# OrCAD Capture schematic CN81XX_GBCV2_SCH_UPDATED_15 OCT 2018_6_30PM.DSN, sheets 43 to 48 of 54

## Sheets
43 47.mSATA CONNECTOR0: size Custom; title: mSATA connector0
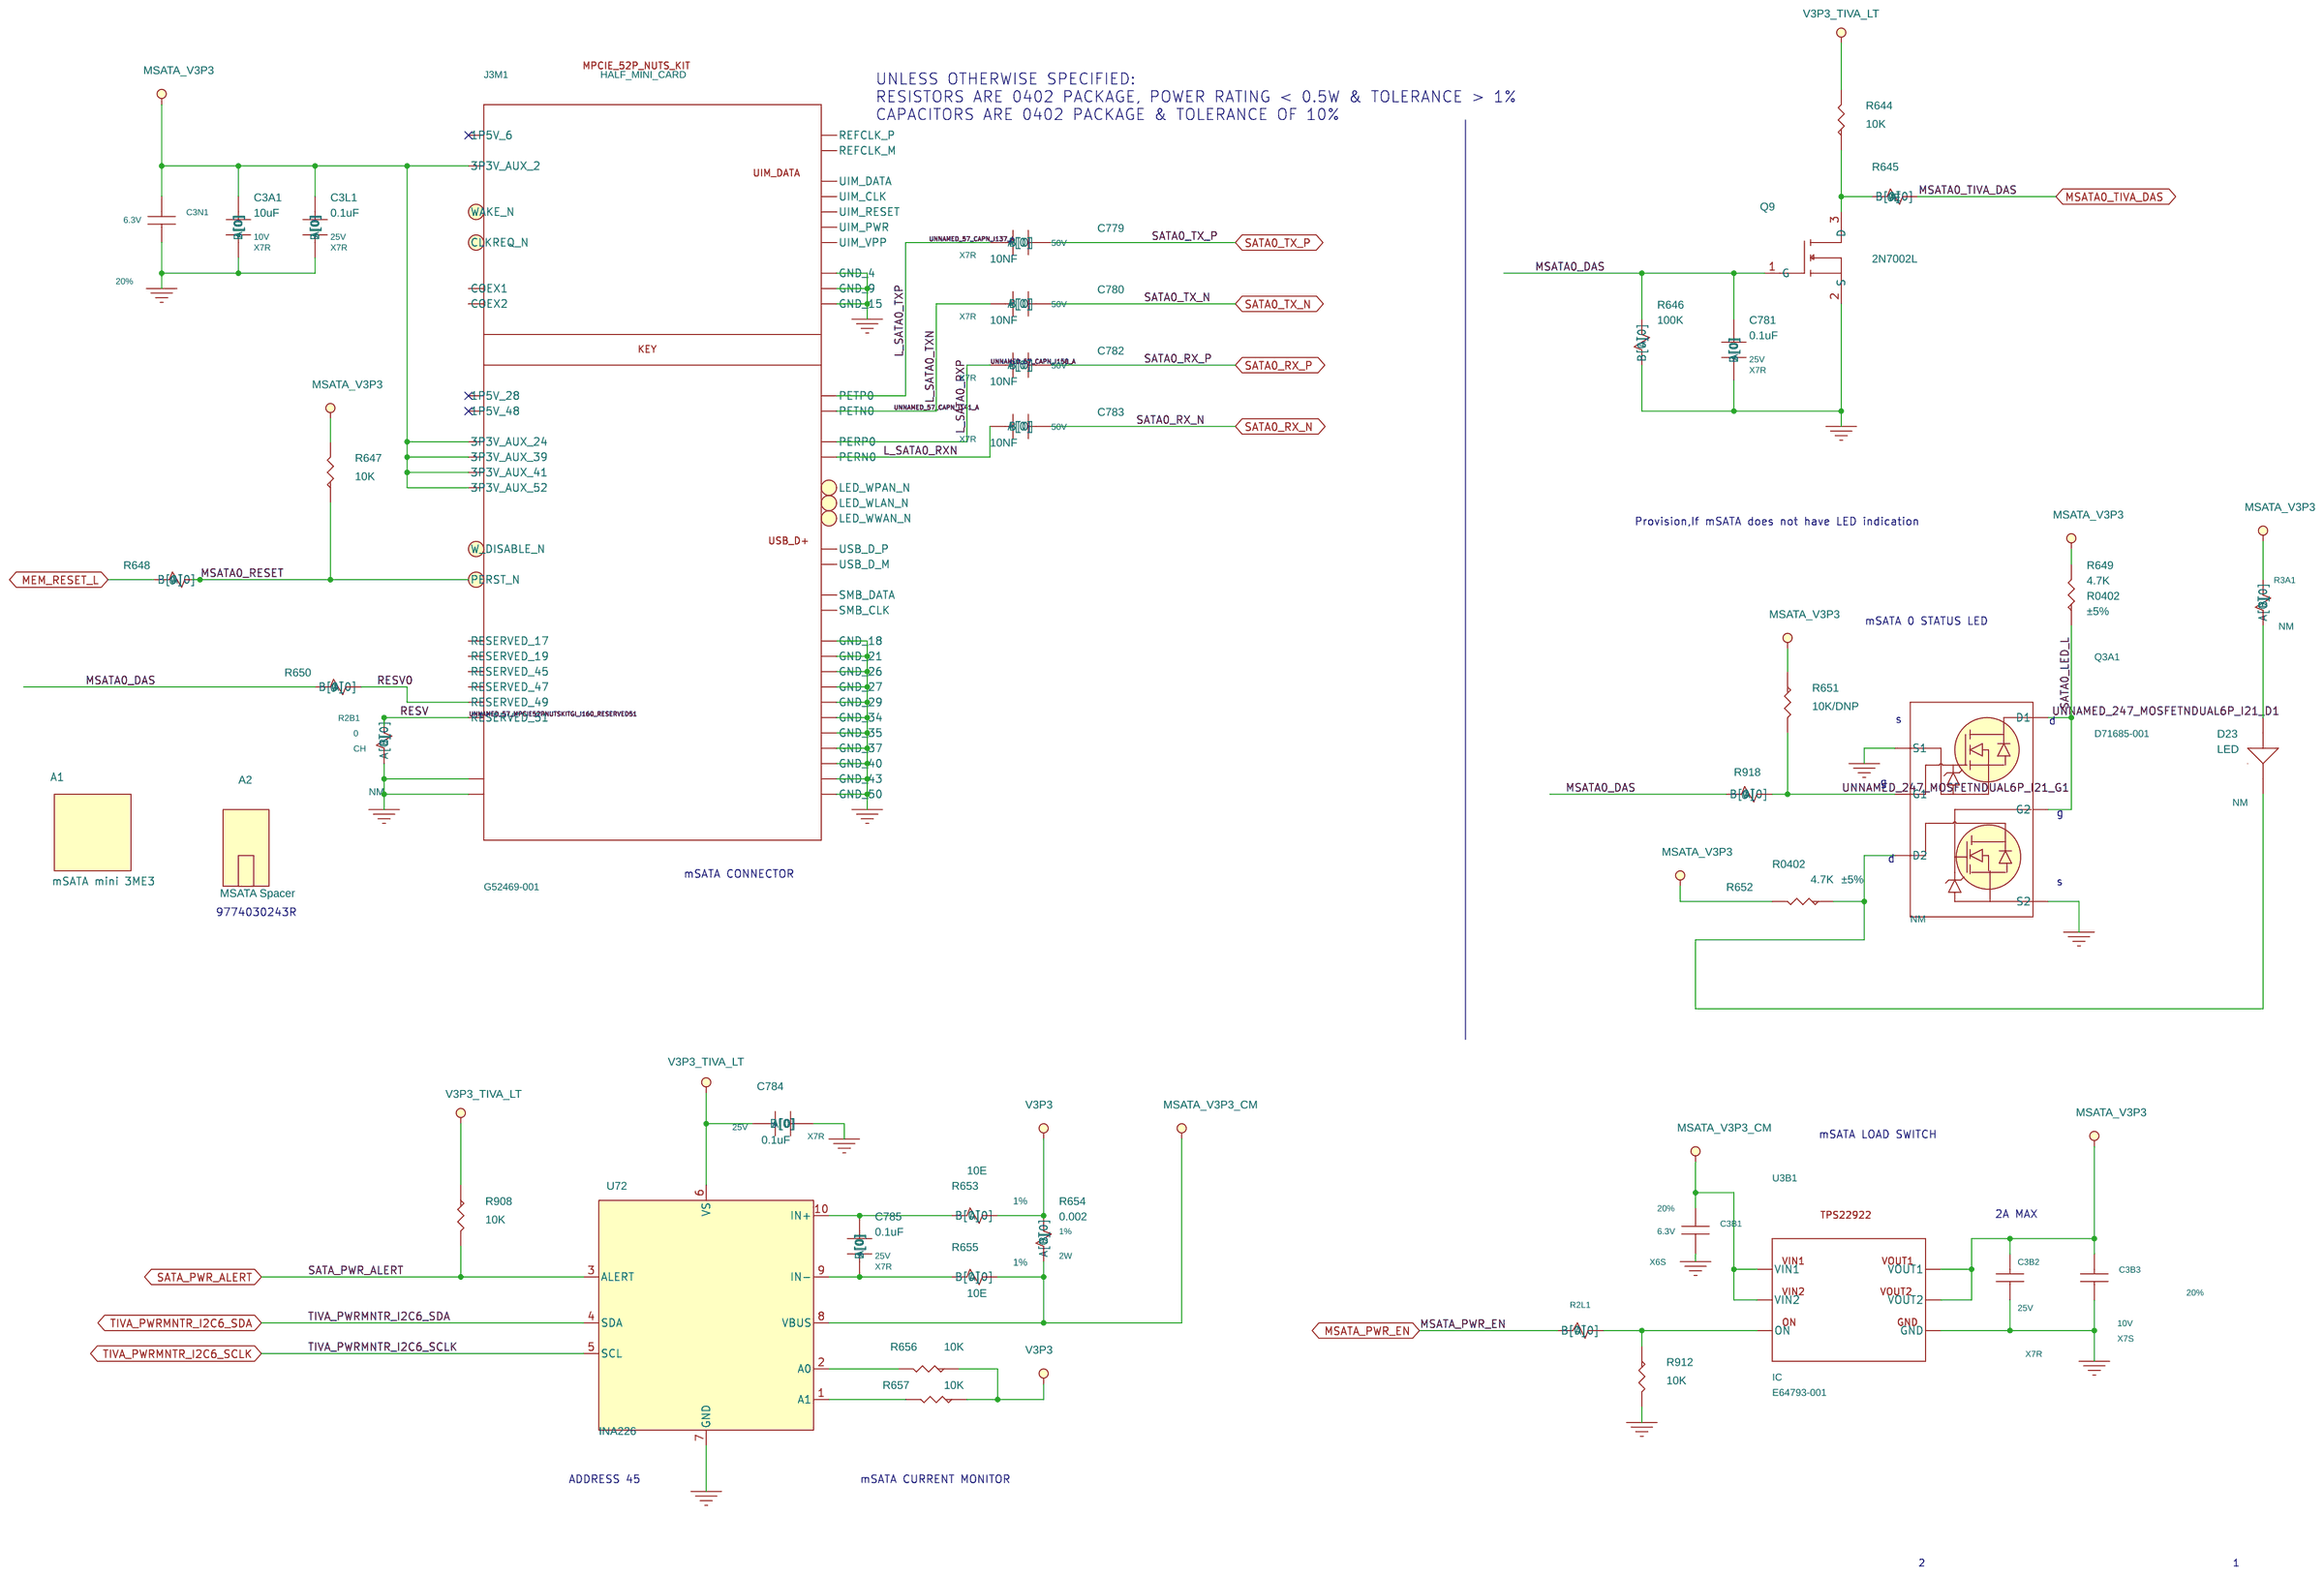
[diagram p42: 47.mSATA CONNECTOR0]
44 48. mSATA CONNECTOR1: size Custom; title: mSATA connector1
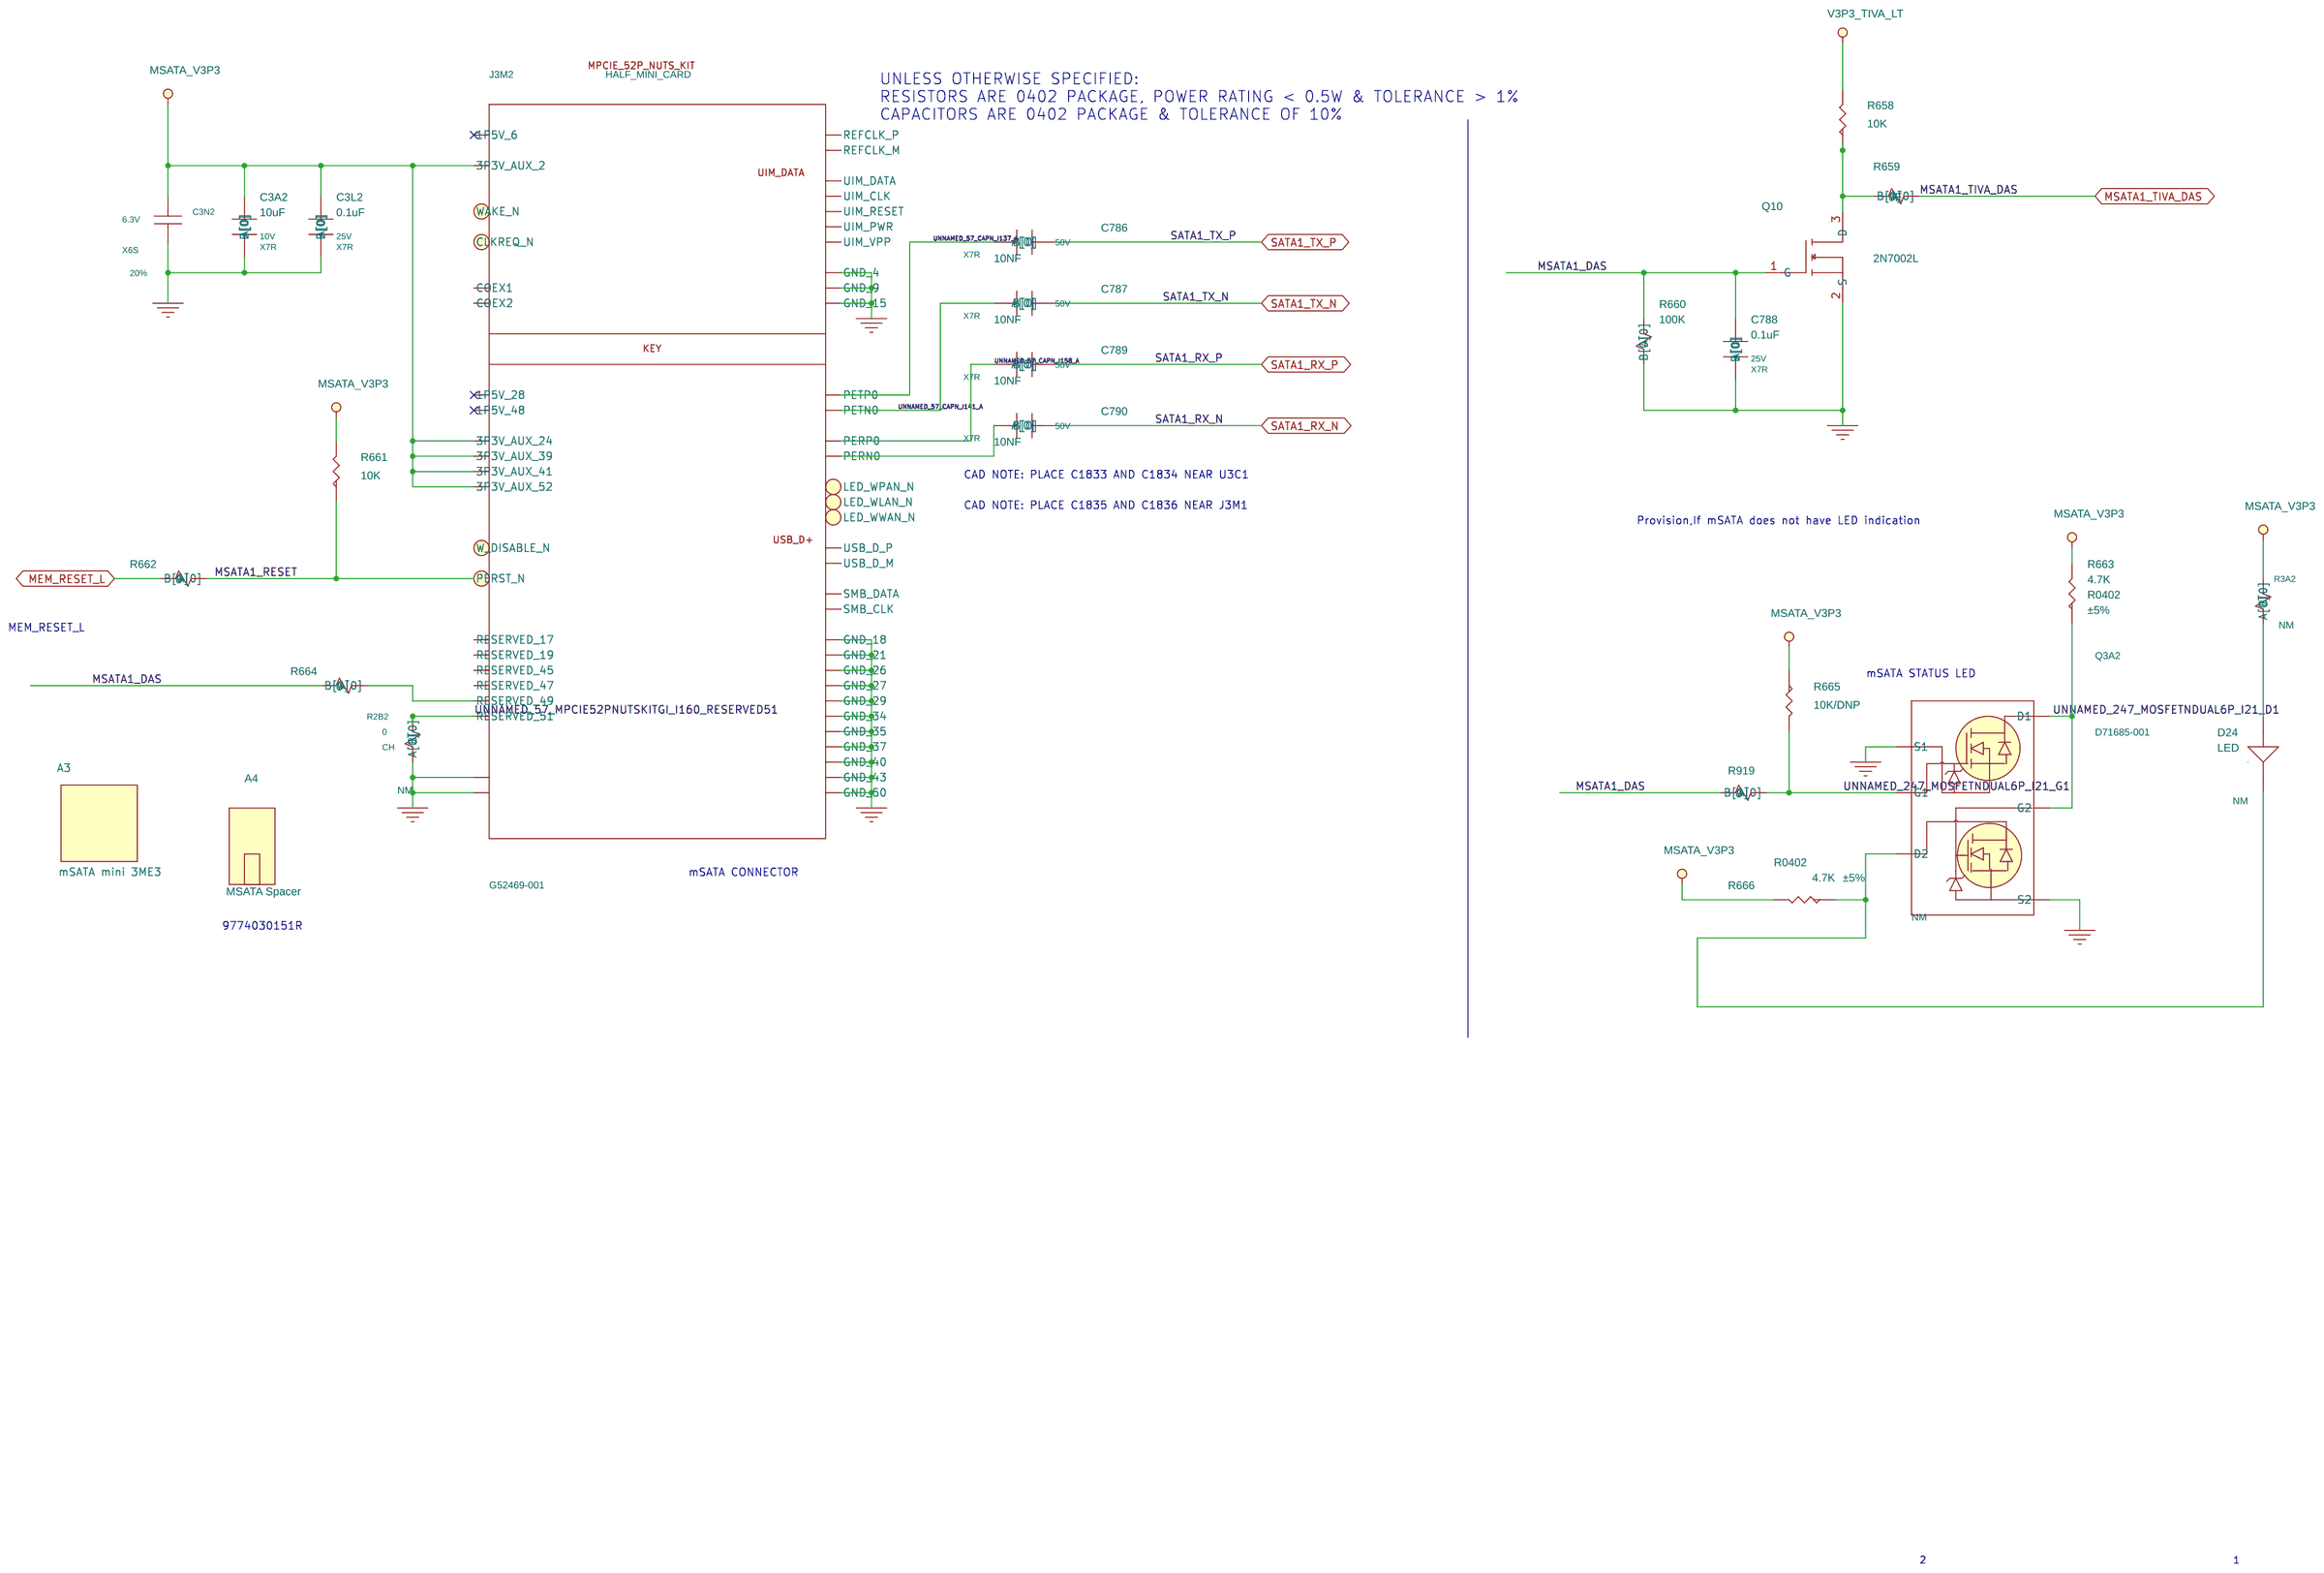
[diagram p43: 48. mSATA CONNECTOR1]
45 49.PTP Module: size B; title: PTP Moduel
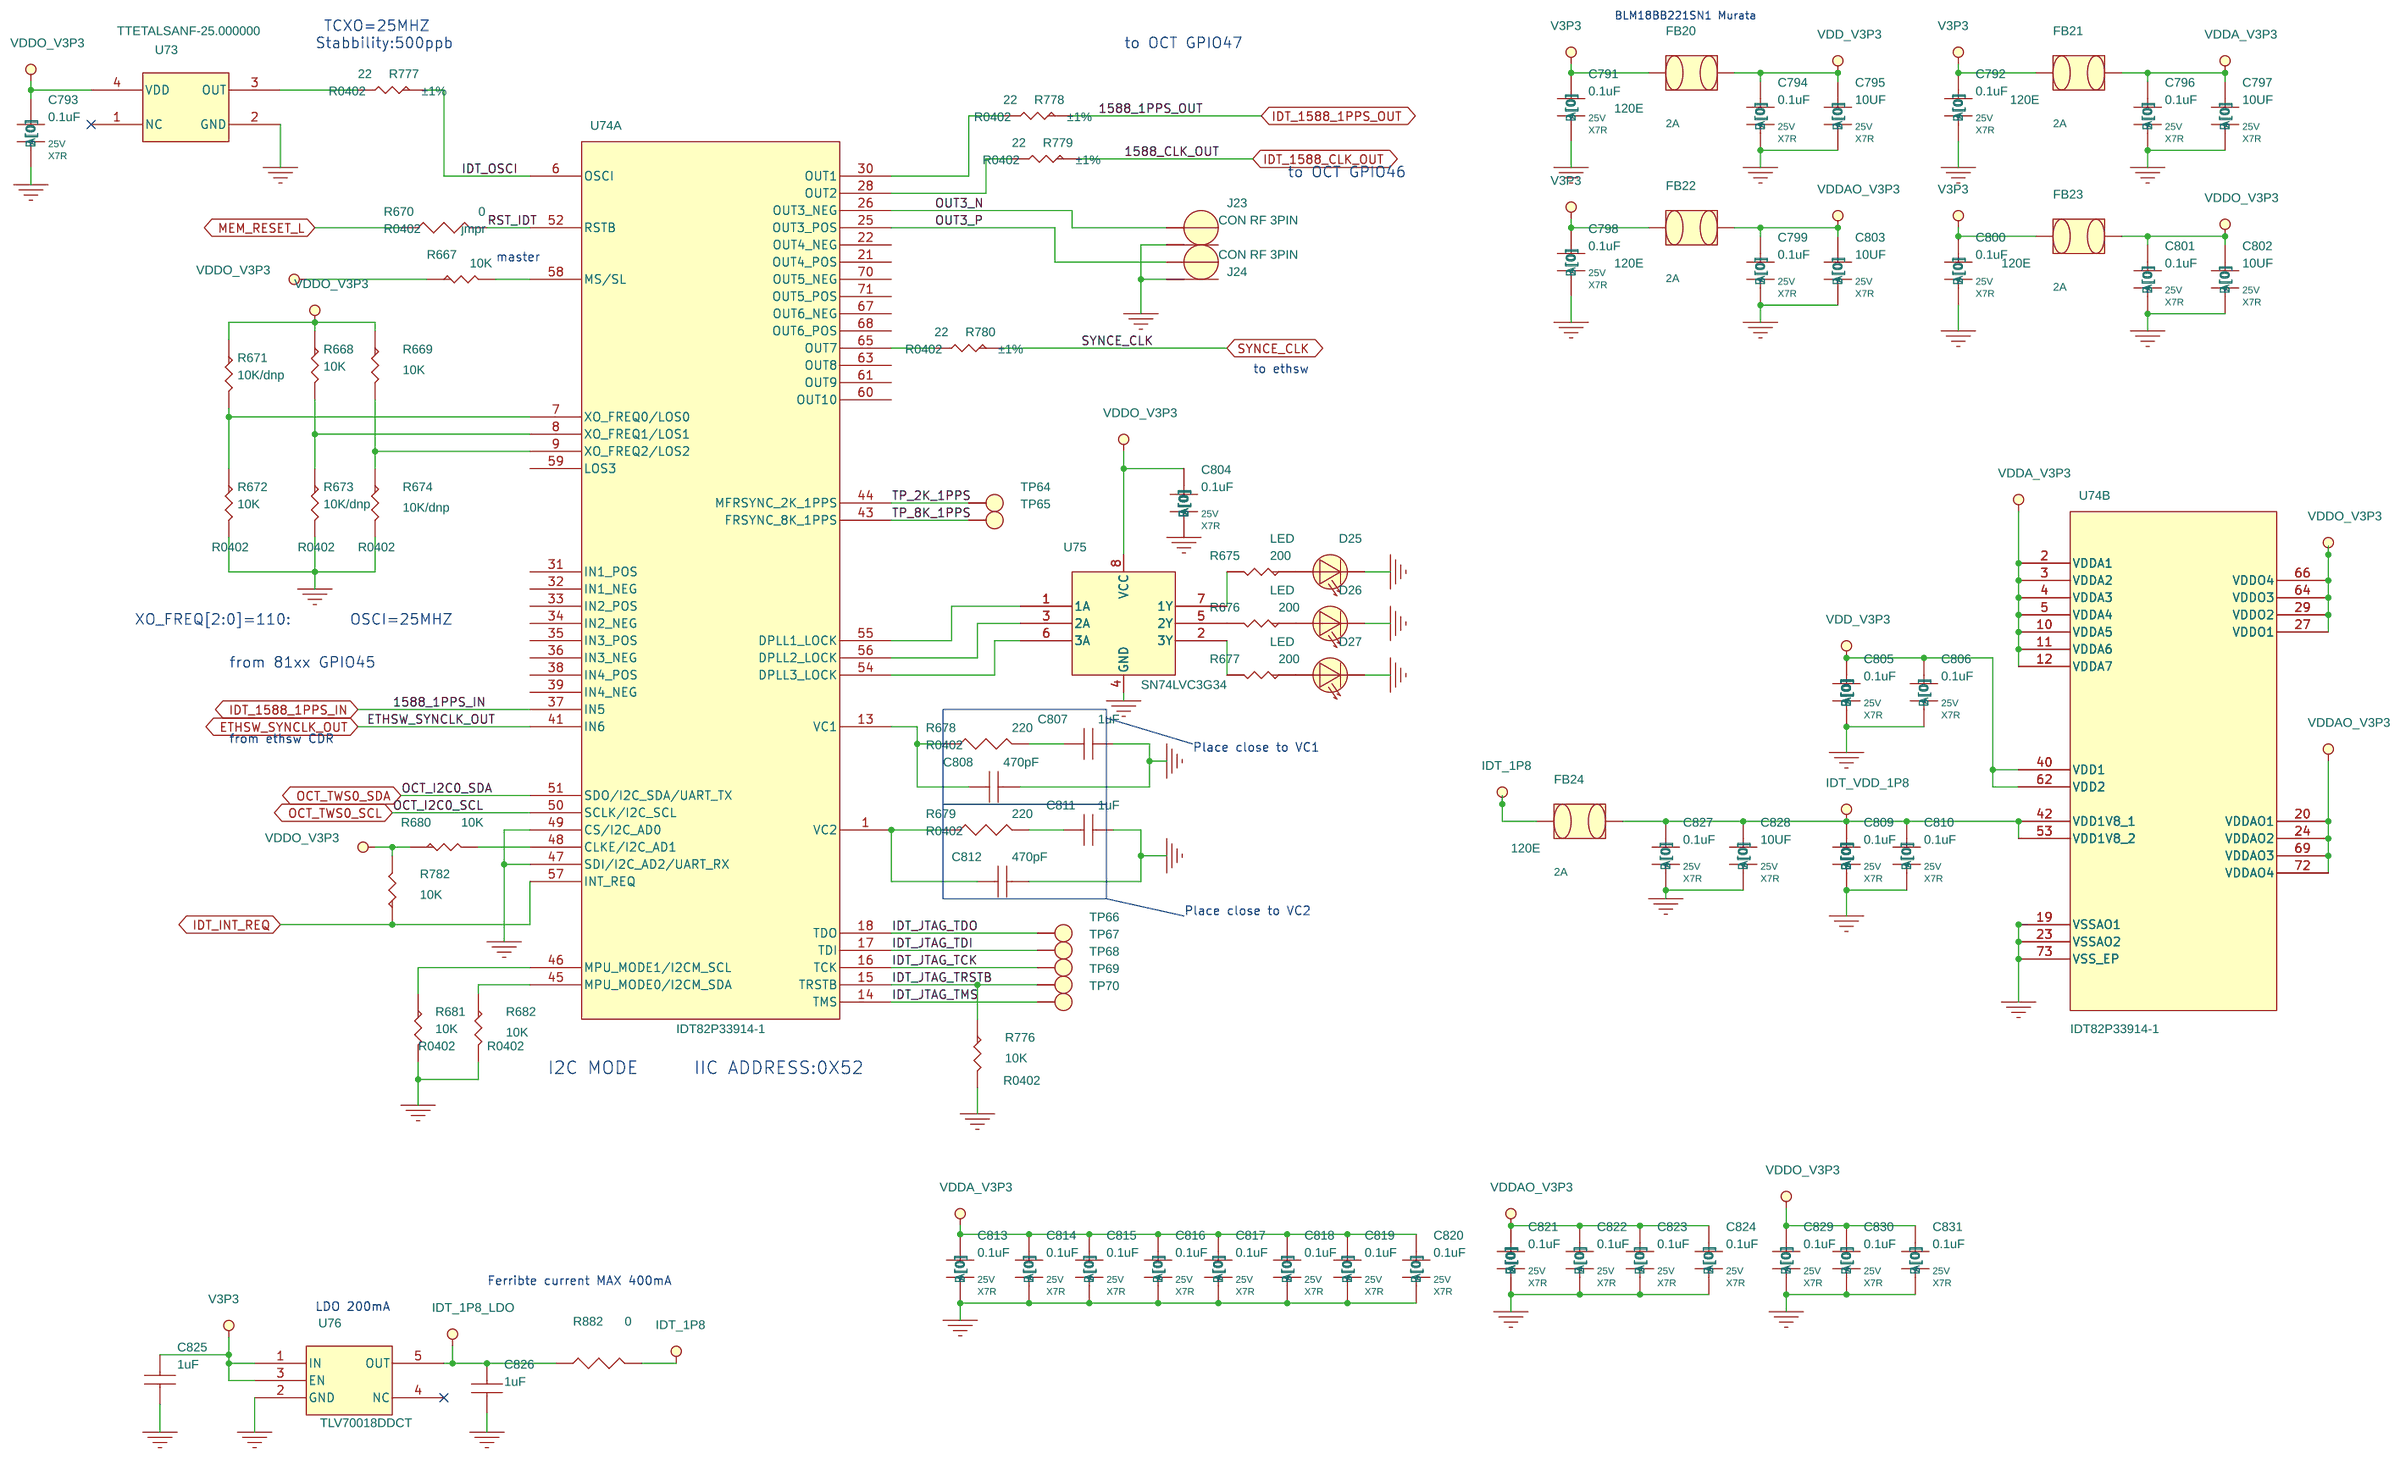
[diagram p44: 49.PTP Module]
46 50.Thermal Sensor & Light Senso: size B; title: TEMP SENSOR
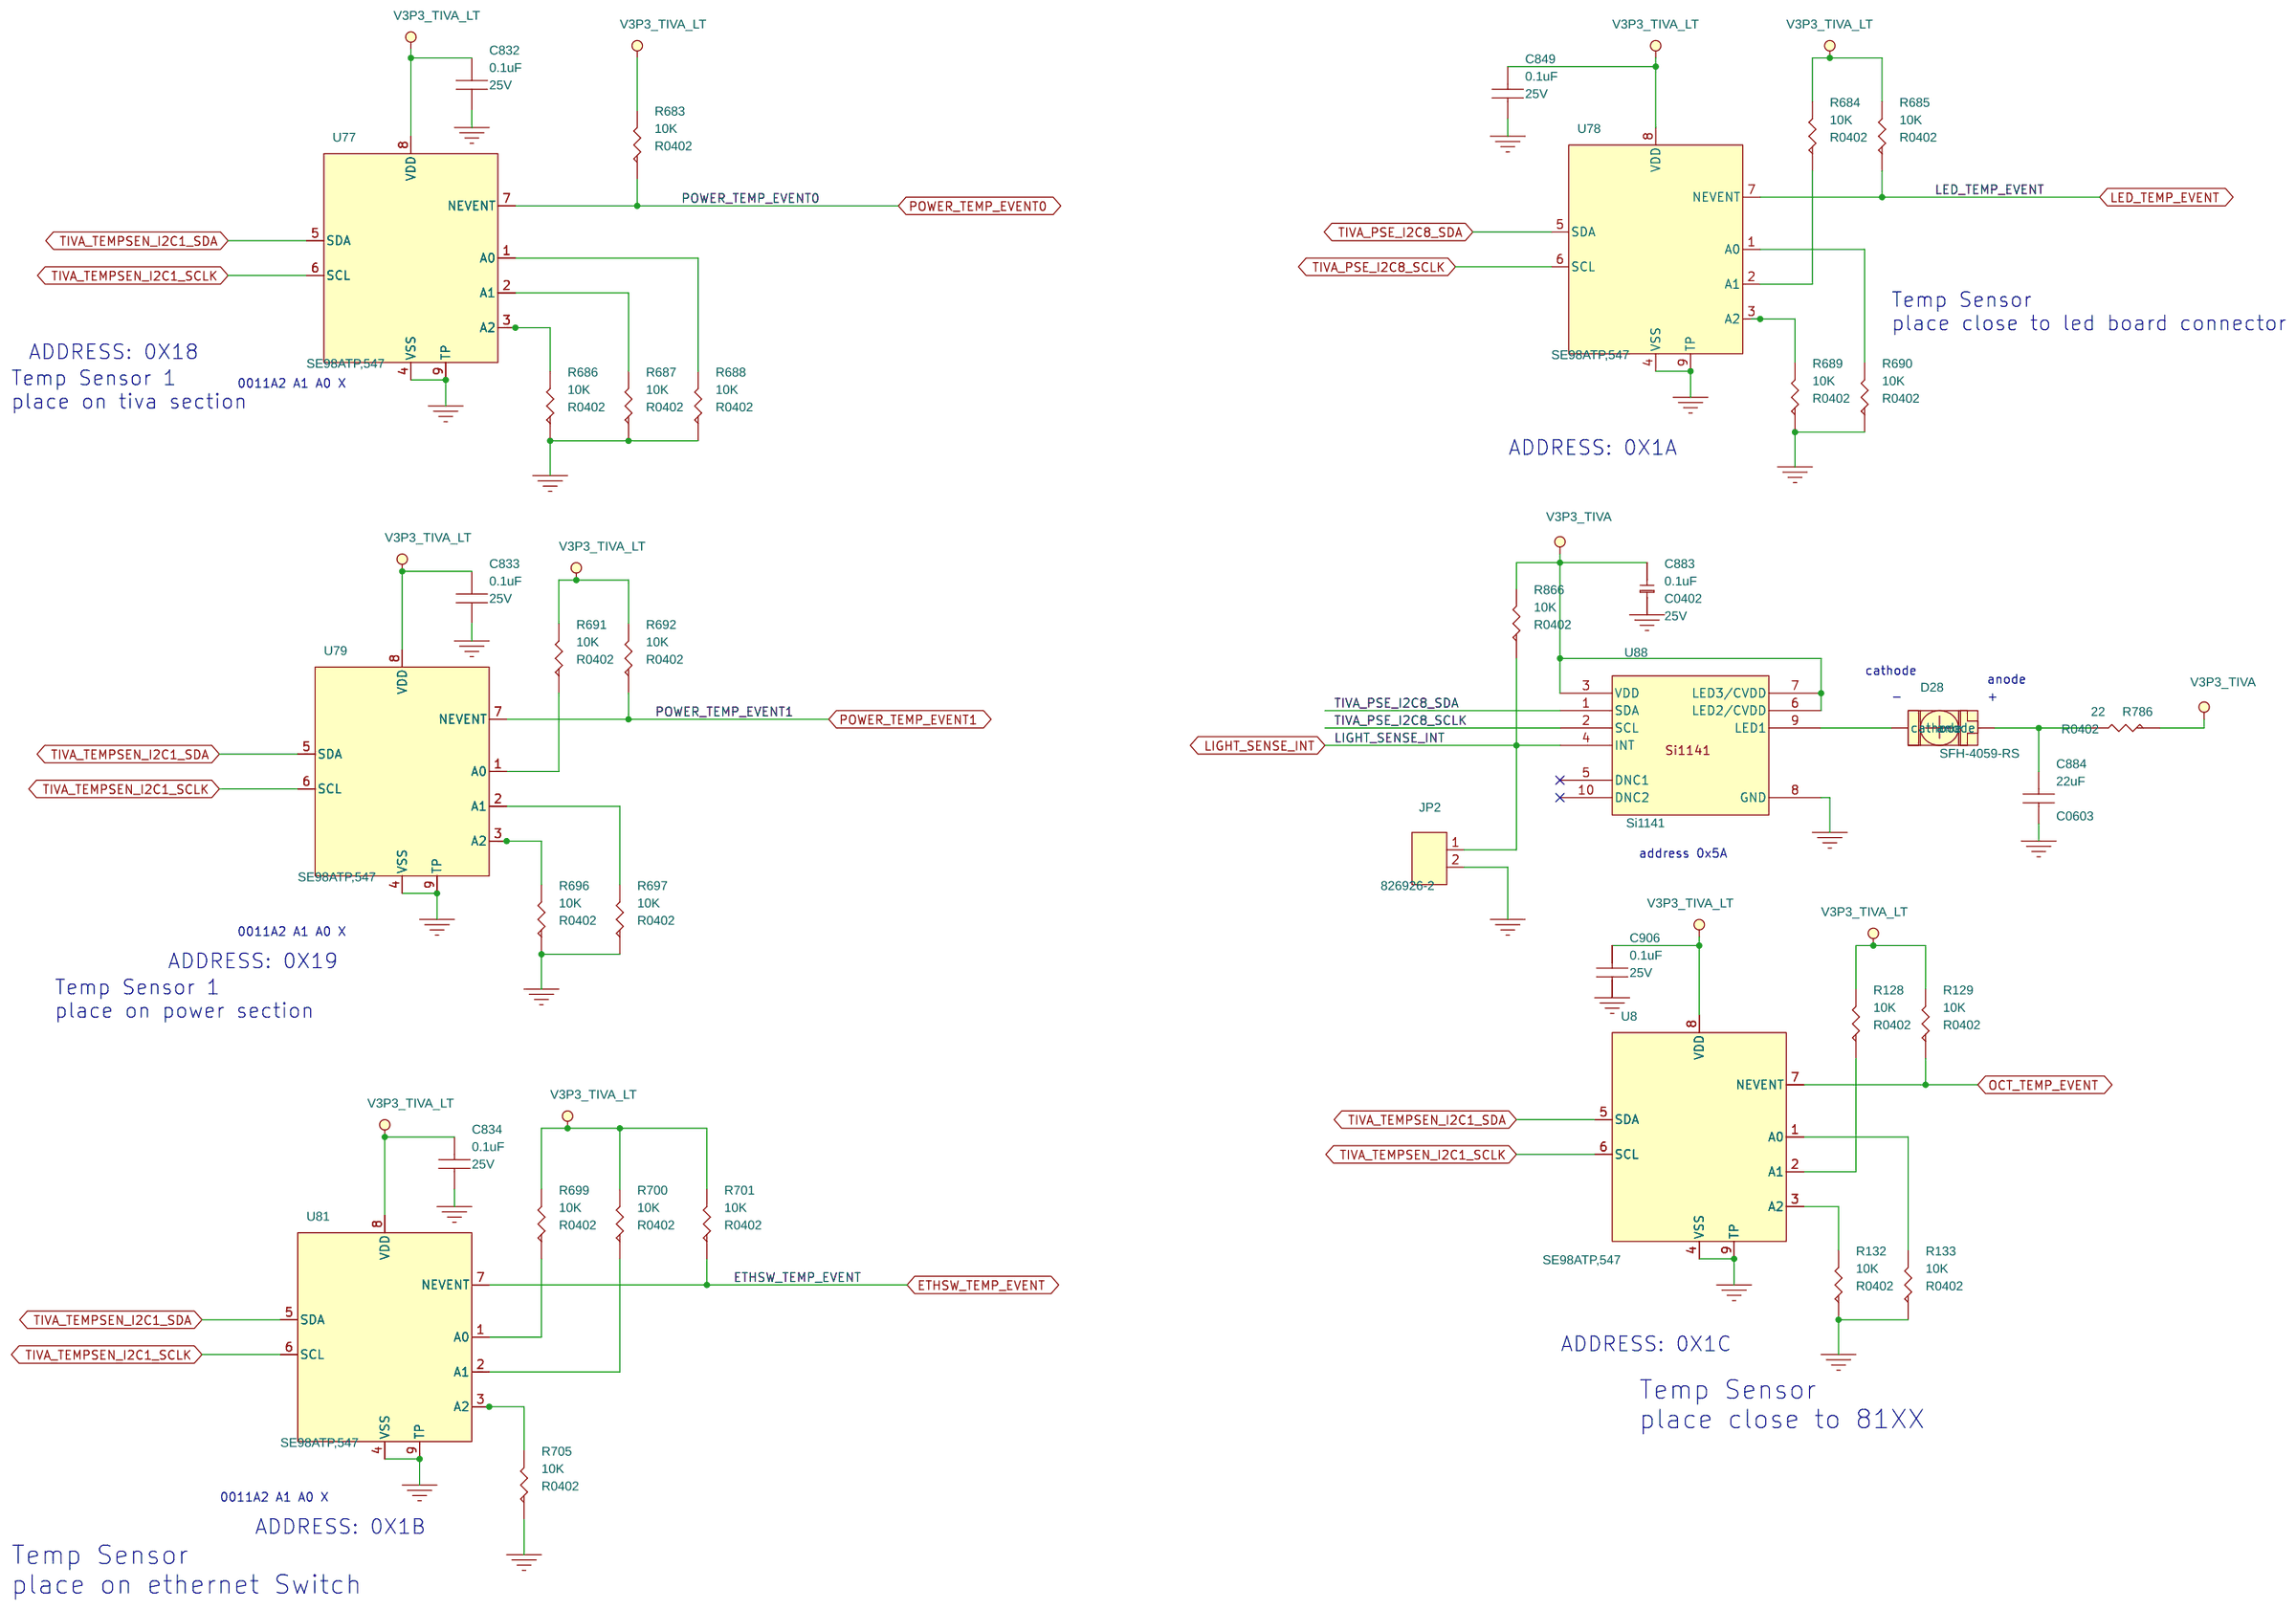
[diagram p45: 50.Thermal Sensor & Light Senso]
47 51.TIVA OCT- IO ISOLATION: size C; title: TIVA OCT-IO ISOLATION
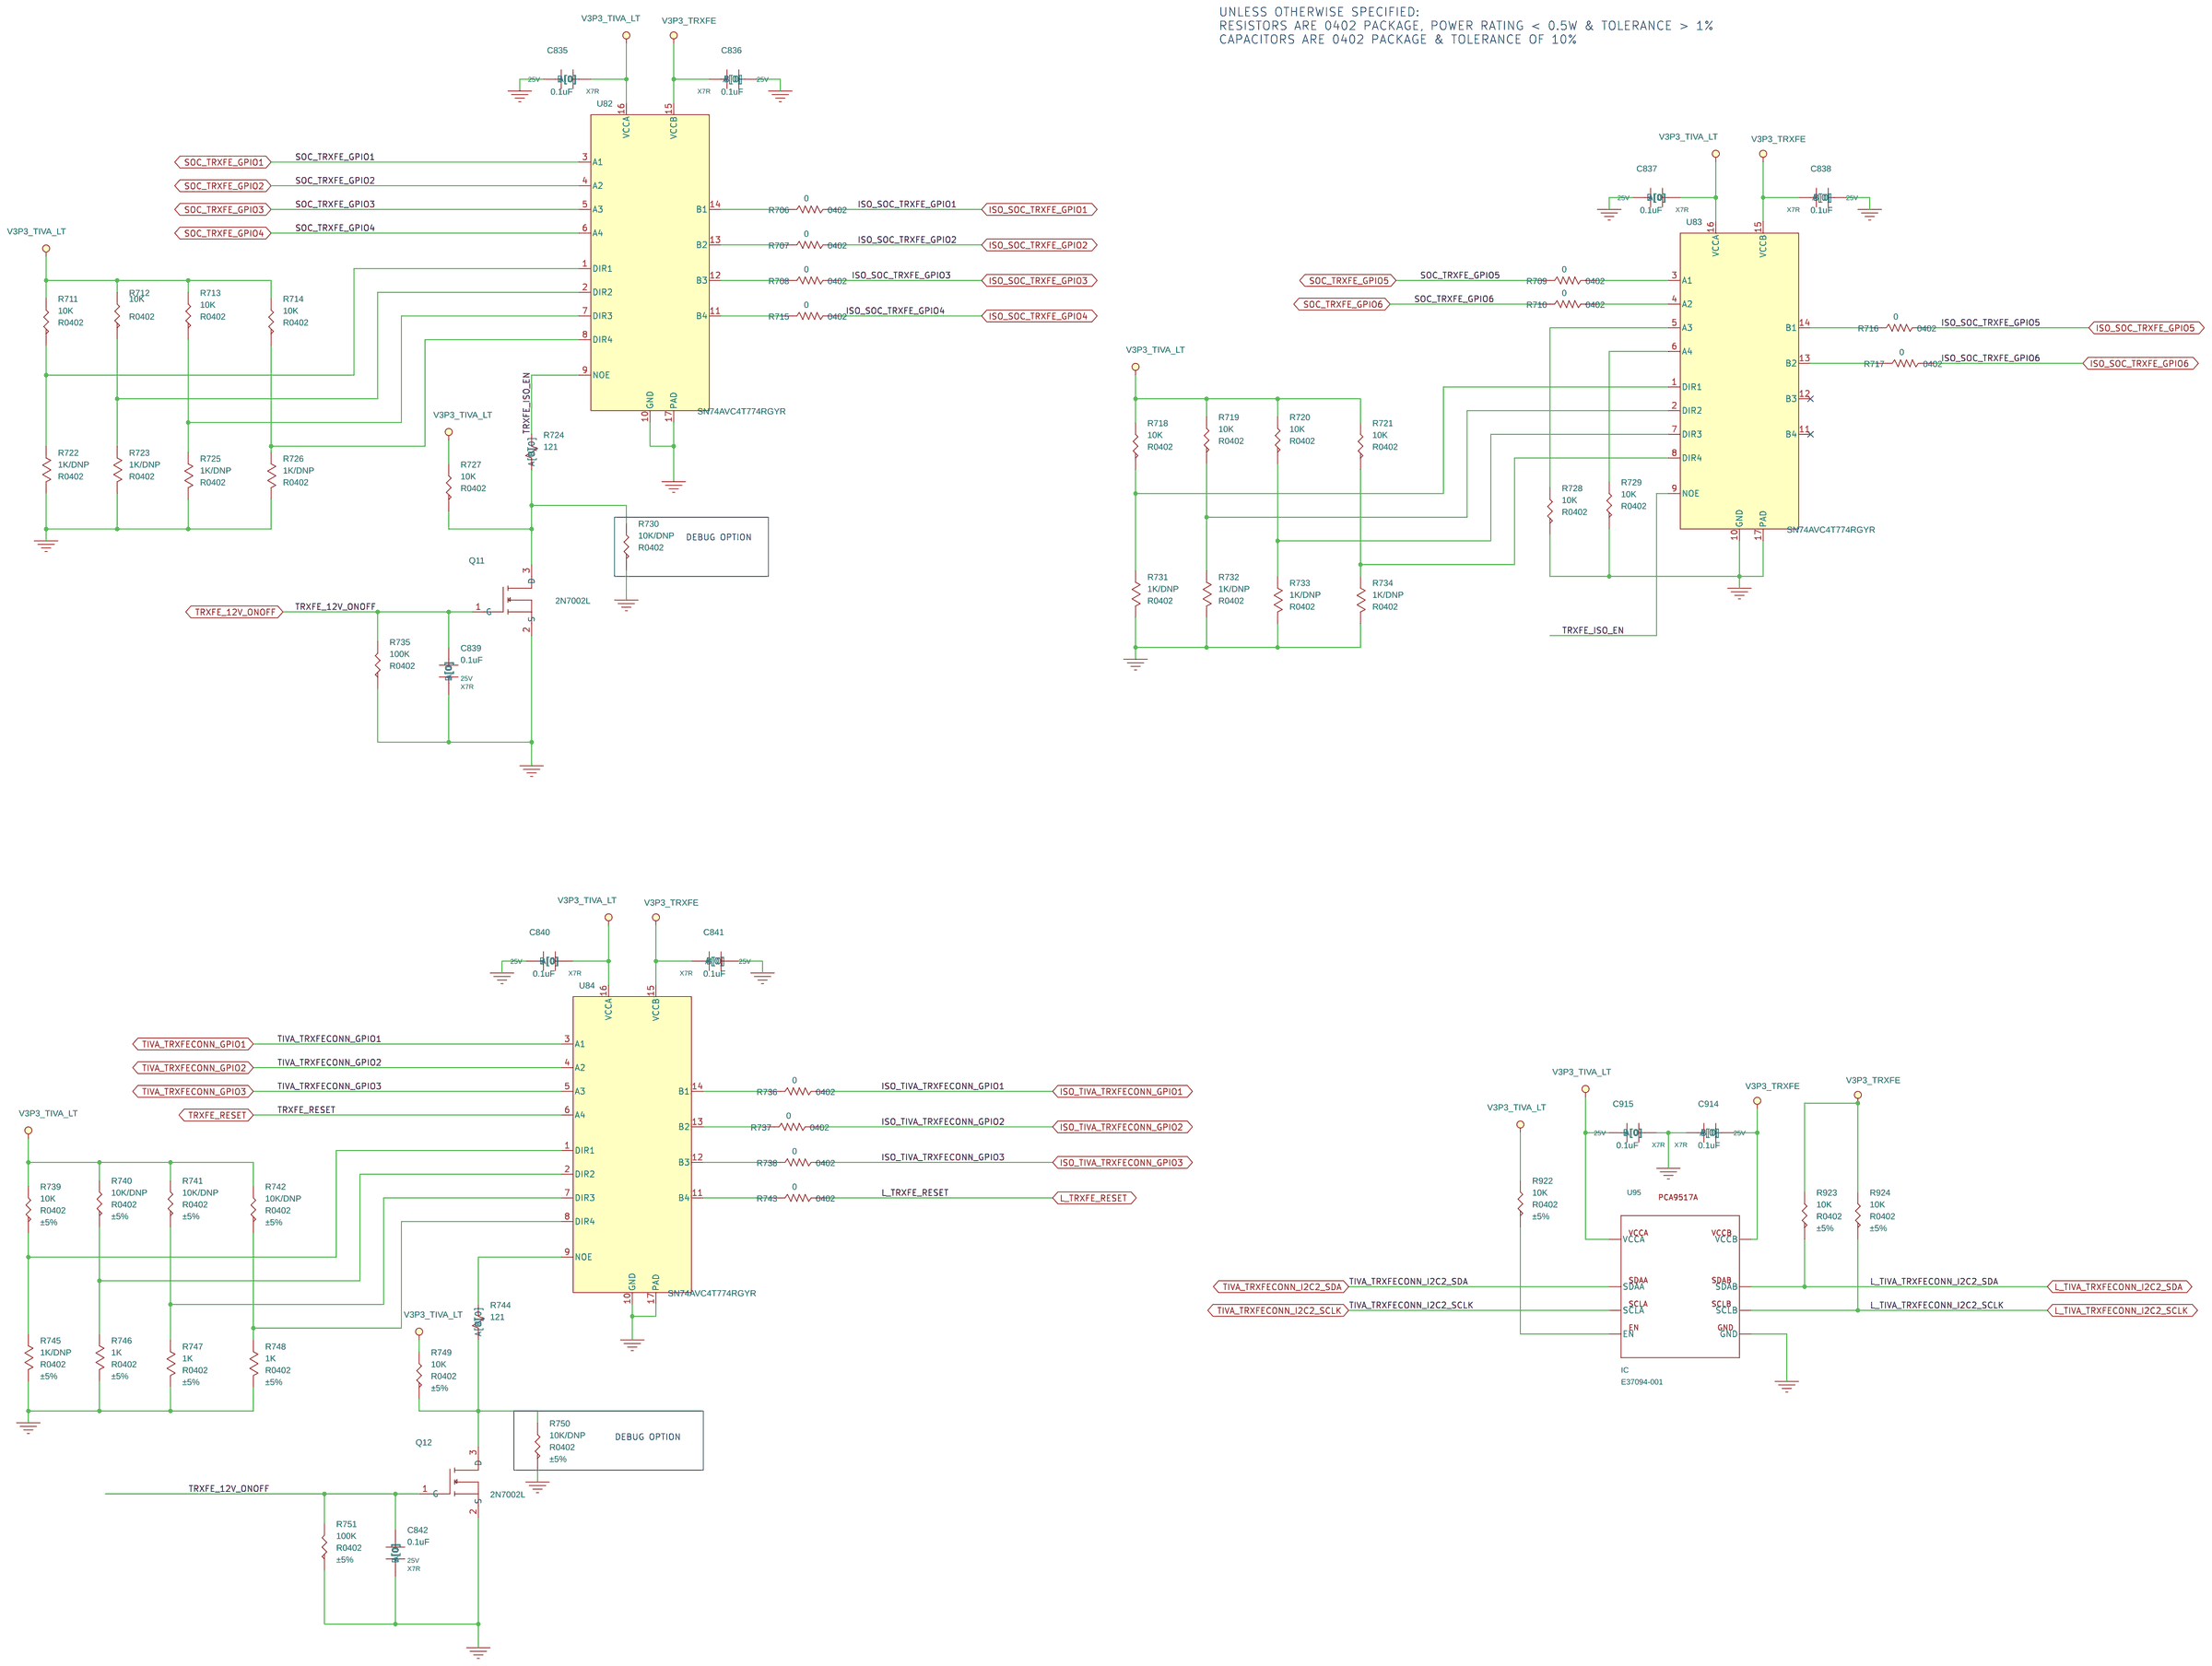
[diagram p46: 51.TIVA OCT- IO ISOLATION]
48 52.TRUSTED PLATFORM MODULE: size B; title: Trusted Platform Modul
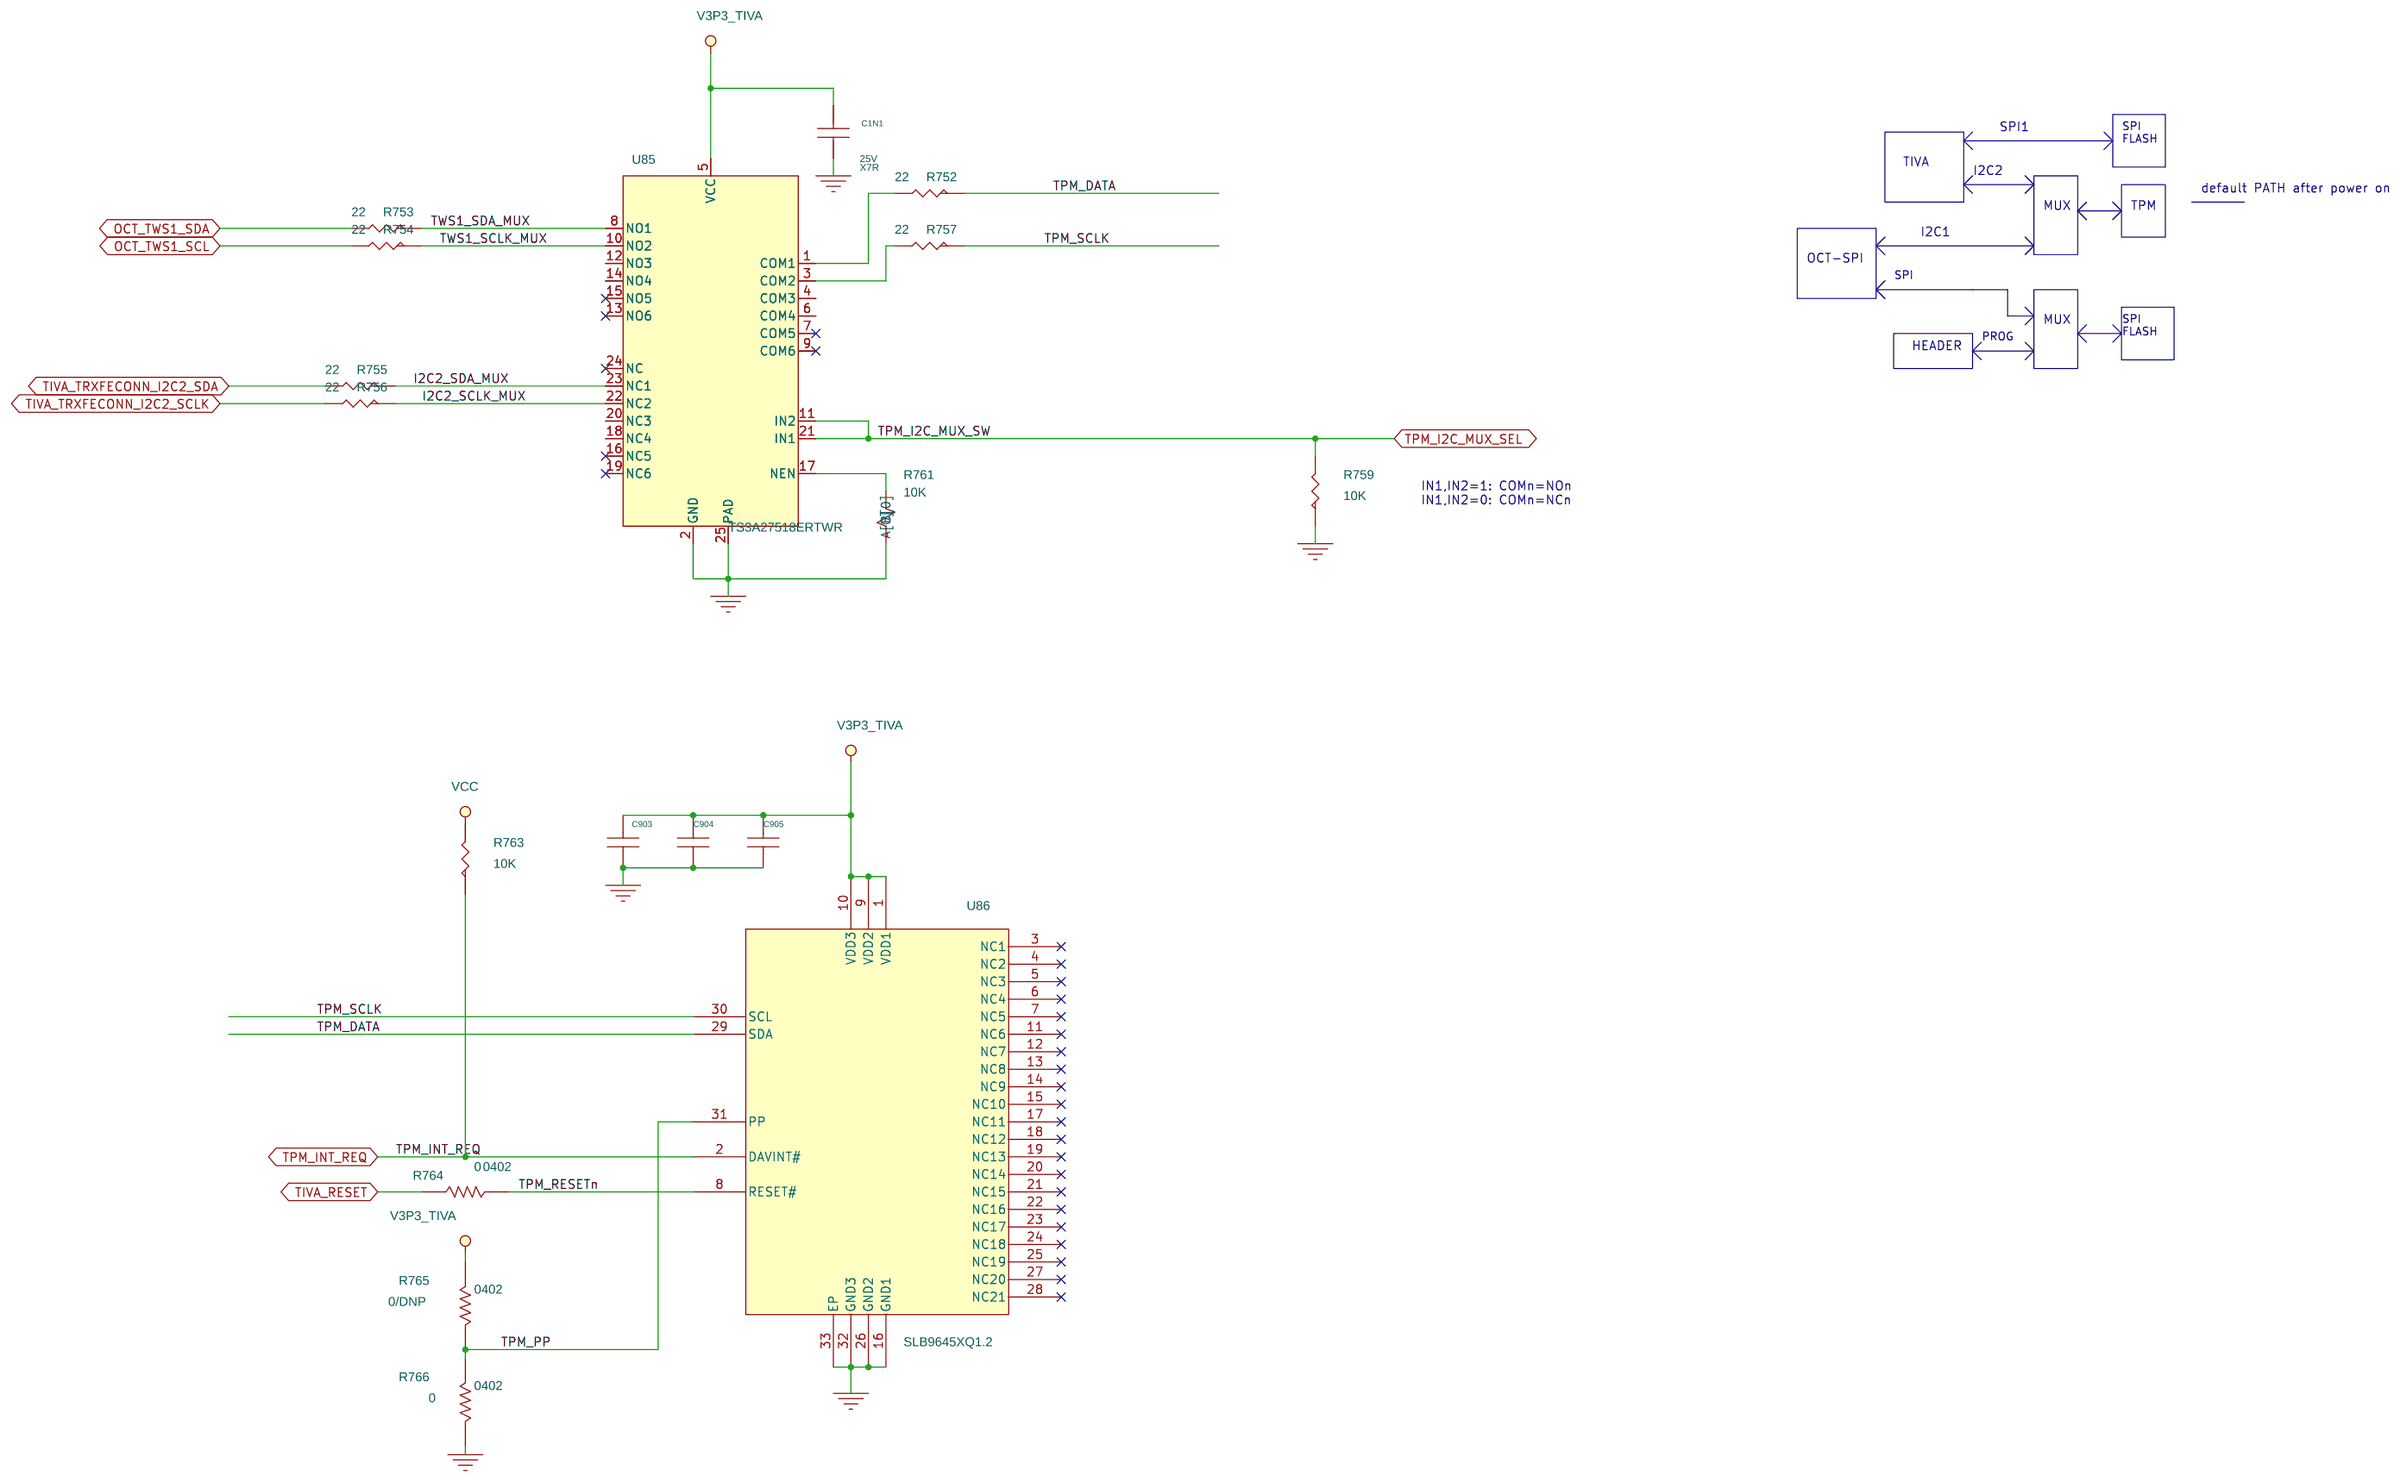
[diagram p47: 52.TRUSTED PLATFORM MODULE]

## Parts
sheet 47.mSATA CONNECTOR0
A1  mSATA mini 3ME3  [MSATA_MINI]
A2  MSATA Spacer  [9774030243R]
C3A1  10uF  [c0603]
C3B1  10UF  [C0402]
C3B2  0.1uF  [C0402]
C3B3  22uF  [C0805]
C3L1  0.1uF  [C0402]
C3N1  22uF  [C0805]
C779  10NF  [C0402]
C780  10NF  [C0402]
C781  0.1uF  [C0402]
C782  10NF  [C0402]
C783  10NF  [C0402]
C784  0.1uF  [C0402]
C785  0.1uF  [C0402]
D23  LED  [LED_LTST-C190]
J3M1  MPCIE_52P_NUTS_KIT_GI  [SKT_MPCIE_HALF_52P_RNUT_PLATED_5P2H_HOLE]
Q3A1  FDG6301N  [SC70_6P]
Q9  2N7002L  [SOT23]
R2B1  0/dnp  [R0402]
R2L1  0E  [R0402]
R3A1  200  [R0402]
R644  10K  [R0402]
R645  0E  [R0402]
R646  100K  [R0402]
R647  10K  [R0402]
R648  0  [R0402]
R649  4.7K  [R0402]
R650  0  [R0402]
R651  10K/DNP  [R0402]
R652  4.7K  [R0402]
R653  10E  [R0402]
R654  0.002  [R2512]
R655  10E  [R0402]
R656  10K  [R0402]
R657  10K  [R0402]
R908  10K  [R0402]
R912  10K  [R0402]
R918  0  [R0402]
U3B1  TPS22925BNYPHR  [DSBGA6N50P2X3_86X136X40]
U72  INA226  [VSSOP50P490X110-10N]
sheet 48. mSATA CONNECTOR1
A3  mSATA mini 3ME3  [MSATA_MINI]
A4  MSATA Spacer  [9774030151R]
C3A2  10uF  [C0603]
C3L2  0.1uF  [C0402]
C3N2  22uF  [C0805]
C786  10NF  [C0402]
C787  10NF  [C0402]
C788  0.1uF  [C0402]
C789  10NF  [C0402]
C790  10NF  [C0402]
D24  LED  [LED_LTST-C190]
J3M2  MPCIE_52P_NUTS_KIT_GI  [SKT_MPCIE_HALF_52P_RNUT_PLATED_5P2H_HOLE_TH]
Q3A2  FDG6301N  [SC70_6P]
Q10  2N7002L  [SOT23]
R2B2  0/dnp  [R0402]
R3A2  200  [R0402]
R658  10K  [R0402]
R659  0E  [R0402]
R660  100K  [R0402]
R661  10K  [R0402]
R662  0  [R0402]
R663  4.7K  [R0402]
R664  0  [R0402]
R665  10K/DNP  [R0402]
R666  4.7K  [R0402]
R919  0  [R0402]
sheet 49.PTP Module
C791  0.1uF  [C0402]
C792  0.1uF  [C0402]
C793  0.1uF  [C0402]
C794  0.1uF  [C0402]
C795  10UF  [cc1206]
C796  0.1uF  [C0402]
C797  10UF  [cc1206]
C798  0.1uF  [C0402]
C799  0.1uF  [C0402]
C800  0.1uF  [C0402]
C801  0.1uF  [C0402]
C802  10UF  [cc1206]
C803  10UF  [cc1206]
C804  0.1uF  [C0402]
C805  0.1uF  [C0402]
C806  0.1uF  [C0402]
C807  1uF  [C0402]
C808  470pF  [C0402]
C809  0.1uF  [C0402]
C810  0.1uF  [C0402]
C811  1uF  [C0402]
C812  470pF  [C0402]
C813  0.1uF  [C0402]
C814  0.1uF  [C0402]
C815  0.1uF  [C0402]
C816  0.1uF  [C0402]
C817  0.1uF  [C0402]
C818  0.1uF  [C0402]
C819  0.1uF  [C0402]
C820  0.1uF  [C0402]
C821  0.1uF  [C0402]
C822  0.1uF  [C0402]
C823  0.1uF  [C0402]
C824  0.1uF  [C0402]
C825  1uF  [C0402]
C826  1uF  [C0402]
C827  0.1uF  [C0402]
C828  10UF  [cc1206]
C829  0.1uF  [C0402]
C830  0.1uF  [C0402]
C831  0.1uF  [C0402]
D25  LED  [D0603]
D26  LED  [D0603]
D27  LED  [D0603]
FB20  120E  [INDC1608X95M]
FB21  120E  [INDC1608X95M]
FB22  120E  [INDC1608X95M]
FB23  120E  [INDC1608X95M]
FB24  120E  [INDC1608X95M]
J23  CON RF 3PIN  [CON-HRS-UFL]
J24  CON RF 3PIN  [CON-HRS-UFL]
R667  10K  [R0402]
R668  10K  [R0402]
R669  10K  [R0402]
R670  0  [R0402]
R671  10K/dnp  [R0402]
R672  10K  [R0402]
R673  10K/dnp  [R0402]
R674  10K/dnp  [R0402]
R675  200  [R0402]
R676  200  [R0402]
R677  200  [R0402]
R678  220  [R0402]
R679  220  [R0402]
R680  10K  [R0402]
R681  10K  [R0402]
R682  10K  [R0402]
R776  10K  [R0402]
R777  22  [R0402]
R778  22  [R0402]
R779  22  [R0402]
R780  22  [R0402]
R782  10K  [R0402]
R882  0  [R1812]
TP64  TP_PWR  [TP_TH_40MIL]
TP65  TP_PWR  [TP_TH_40MIL]
TP66  TP_PWR  [SMD20-A]
TP67  TP_PWR  [SMD20-A]
TP68  TP_PWR  [SMD20-A]
TP69  TP_PWR  [SMD20-A]
TP70  TP_PWR  [SMD20-A]
U73  TTETALSANF-25.000000  [TETALSANF-25]
U74  IDT82P33914-1  [IDT82P33913-1]  (sections A,B)
U75  SN74LVC3G34  [VSSOP8-05-3]
U76  TLV70018DDCT  [SOT-23-THIN]
sheet 50.Thermal Sensor & Light Senso
C832  0.1uF  [C0402]
C833  0.1uF  [C0402]
C834  0.1uF  [C0402]
C849  0.1uF  [C0402]
C883  0.1uF  [C0402]
C884  22uF  [C0603]
C906  0.1uF  [C0402]
D28  SFH-4059-RS  [SFH-4059-RS]
JP2  826926-2  [SAMTEC_TSW-102-07-T-S]
R128  10K  [R0402]
R129  10K  [R0402]
R132  10K  [R0402]
R133  10K  [R0402]
R683  10K  [R0402]
R684  10K  [R0402]
R685  10K  [R0402]
R686  10K  [R0402]
R687  10K  [R0402]
R688  10K  [R0402]
R689  10K  [R0402]
R690  10K  [R0402]
R691  10K  [R0402]
R692  10K  [R0402]
R696  10K  [R0402]
R697  10K  [R0402]
R699  10K  [R0402]
R700  10K  [R0402]
R701  10K  [R0402]
R705  10K  [R0402]
R786  22  [R0402]
R866  10K  [R0402]
U8  SE98ATP,547  [SON50P300X200X80-9N_NXP]
U77  SE98ATP,547  [SON50P300X200X80-9N_NXP]
U78  SE98ATP,547  [SON50P300X200X80-9N_NXP]
U79  SE98ATP,547  [SON50P300X200X80-9N_NXP]
U81  SE98ATP,547  [SON50P300X200X80-9N_NXP]
U88  Si1141  [QFN10-050-2020L]
sheet 51.TIVA OCT- IO ISOLATION
C835  0.1uF  [C0402]
C836  0.1uF  [C0402]
C837  0.1uF  [C0402]
C838  0.1uF  [C0402]
C839  0.1uF  [C0402]
C840  0.1uF  [C0402]
C841  0.1uF  [C0402]
C842  0.1uF  [C0402]
C914  0.1uF  [C0402]
C915  0.1uF  [C0402]
Q11  2N7002L  [SOT23]
Q12  2N7002L  [SOT23]
R706  0  [R0402]
R707  0  [R0402]
R708  0  [R0402]
R709  0  [R0402]
R710  0  [R0402]
R711  10K  [R0402]
R712  10K  [R0402]
R713  10K  [R0402]
R714  10K  [R0402]
R715  0  [R0402]
R716  0  [R0402]
R717  0  [R0402]
R718  10K  [R0402]
R719  10K  [R0402]
R720  10K  [R0402]
R721  10K  [R0402]
R722  1K/DNP  [R0402]
R723  1K/DNP  [R0402]
R724  121  [R0402]
R725  1K/DNP  [R0402]
R726  1K/DNP  [R0402]
R727  10K  [R0402]
R728  10K  [R0402]
R729  10K  [R0402]
R730  10K/DNP  [R0402]
R731  1K/DNP  [R0402]
R732  1K/DNP  [R0402]
R733  1K/DNP  [R0402]
R734  1K/DNP  [R0402]
R735  100K  [R0402]
R736  0  [R0402]
R737  0  [R0402]
R738  0  [R0402]
R739  10K  [R0402]
R740  10K/DNP  [R0402]
R741  10K/DNP  [R0402]
R742  10K/DNP  [R0402]
R743  0  [R0402]
R744  121  [R0402]
R745  1K/DNP  [R0402]
R746  1K  [R0402]
R747  1K  [R0402]
R748  1K  [R0402]
R749  10K  [R0402]
R750  10K/DNP  [R0402]
R751  100K  [R0402]
R922  10K  [R0402]
R923  10K  [R0402]
R924  10K  [R0402]
U82  SN74AVC4T774RGYR  [VQFN50P400X350X100-17N_TI]
U83  SN74AVC4T774RGYR  [VQFN50P400X350X100-17N_TI]
U84  SN74AVC4T774RGYR  [VQFN50P400X350X100-17N_TI]
U95  PCA9517A  [SSOP8_65MM_3W]
sheet 52.TRUSTED PLATFORM MODULE
C1N1  0.1uF  [R0402]
C903  0.1uF  [C0402]
C904  0.1uF  [C0402]
C905  0.1uF  [C0402]
R752  22  [R0402]
R753  22  [R0402]
R754  22  [R0402]
R755  22  [R0402]
R756  22  [R0402]
R757  22  [R0402]
R759  10K  [R0402]
R761  10K  [R0402]
R763  10K  [R0402]
R764  0  [R0402]
R765  0/DNP  [R0402]
R766  0  [R0402]
U85  TS3A27518ERTWR  [TS3A27518ERTWR]
U86  SLB9645XQ1.2  [PG-VQFN-32-13]

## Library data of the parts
A1 A3 = mSATA_mini_3ME3: mSATA Drive; Manufacturer: InnoDisk; Part Number: DEMSM-64GD09BW1DC-AT
A2 = 4-881545-2_0: ROUND STANDOFF M2 STEEL 3MM; Alt.Part Number: 4-881545-2; Manufacturer: Wurth Electronics Inc
C3A1 = CAP_CER_0.1UF_10V_10%_X5R_0402: CAP CER 10UF 10V X7T 0603; MATERIAL: X7R; Manufacturer: murata; PART_NUMBER: 0.1UF; Part Number: GRM188D71A106MA73D; TOLERANCE: 10%; VOLTAGE: 10V
C3B1 = cap_0402_0.1uF_16V_10%_X7R: CAP CER 10UF 6.3V X6S 0402; MATERIAL: X6S; MFG: MURATA; MFG_PN: GRM155R60J106ME44; Manufacturer: Murata Electronics North America; PART_NUMBER: G21049-001; PATH: I86; PHYS_PAGE: 50; Part Number: GRM155C80J106ME11D; TOLERANCE: 20%; VOLTAGE: 6.3V; XY: -29,251,100
C3B2 = cap_0402_0.1uF_16V_10%_X7R: CAP CER 0.1UF 25V 10% X7R 0402; MATERIAL: X7R; MFG: MURATA; MFG_PN: GRM155R71C104KA88J; Manufacturer: MURATA; Manufacturer Part Number: GRM155R71C104KA88D; PART_NUMBER: A36096-030; PATH: I87; PHYS_PAGE: 50; Part Number: C1005X7R1E104K050BB; TOLERANCE: 10%; VOLTAGE: 25V; XY: -3,950,950
C3B3 = cap_0402_0.1uF_16V_10%_X7R: CAP CER 22UF 10V X7S 0805; MATERIAL: X7S; MFG: SAMSUNG; MFG_PN: C2012X7S1A226M125AC; Manufacturer: TDK Corporation; PART_NUMBER: 602433-081; PATH: I134; PHYS_PAGE: 50; Part Number: C2012X7S1A226M125AC; TOLERANCE: 20%; VOLTAGE: 10V; XY: -4,225,950
C3L1 C3L2 C781 C784 C785 C788 C791-C794 C796 C798-C801 C804-C806 C809 C810 C813-C824 C827 C829-C831 C835-C842 C914 C915 = CAP_CER_0.1UF_10V_10%_X5R_0402: CAP CER 0.1UF 25V 10% X7R 0402; MATERIAL: X7R; Manufacturer: MURATA; Manufacturer Part Number: GRM155R71C104KA88D; PART_NUMBER: 0.1UF; Part Number: C1005X7R1E104K050BB; TOLERANCE: 10%; VOLTAGE: 25V
C3N1 C3N2 = cap_0402_0.1uF_16V_10%_X7R: 22µF ±20% 10V X6S Ceramic Capacitor; MATERIAL: X6S; MFG: SAMSUNG; MFG_PN: CL10A226MQ8NRNE; Manufacturer: TDK Corporation; PART_NUMBER: 602433-081; PATH: I326; PHYS_PAGE: 15; Part Number: C2012X6S1A226M125AC; TOLERANCE: 20%; VOLTAGE: 6.3V; XY: -3,001,675
C779 C780 C782 C783 C786 C787 C789 = CAP_CER_0.1UF_10V_10%_X5R_0402: CAP CER 10000PF 50V X7R 0402; MATERIAL: X7R; Manufacturer: Murata Electronics North America; PART_NUMBER: 0.1UF; Part Number: GRM155R71H103KA88D; TOLERANCE: 10%; VOLTAGE: 50V
D23 D24 = LED_wp117_1: LED GREEN DIFFUSED 0603 SMD; Manufacturer: Lumex; Manufacturer Part Number: SML-LX0603GW-TR; No_Mount: NM; Part Number: LTST-C190KGKT
J3M1 J3M2 = MPCIE_52P_NUTS_KIT_GI_6: Mini PCI-E 5.2H 52Pin 0.8mm Pitch,SMT, R/A, Black, RoHS; MATERIAL: KIT; MFG: LOTES; MFG_PN: AAA-PCI-092-Y01; Manufacturer: LOTES; Manufacturer Part Number: AAA-PCI-092-Y01; PART_CONFIG: HALF_MINI_CARD; PART_NUMBER: G52469-001; PATH: I160; PHYS_PAGE: 26; Part Number: AAA-PCI-092-Y01; XY: (1350,3300)
Q3A1 Q3A2 = MOSFETN_DUAL_6P: MOSFET 2N-CH 25V 0.22A SC70-6; MFG: FAIRCHILD SEMICONDUCTOR; Manufacturer: FAIRCHILD SEMICONDUCTOR; No_Mount: NM; PART_NUMBER: D71685-001; PATH: I21; PHYS_PAGE: 35; XY: (-4775,1350)
Q9-Q12 = 2N7002L_1: MOSFET N-CH 60V 115MA SOT23-3; Manufacturer: Diodes Inc; Manufacturer Part Number: 2N7002-7-F; Part Number: 2N7002-7-F
R2B1 R2B2 = RESN: MATERIAL: CH; MFG: KOA SPEER; MFG_PN: RK73Z1ETTP; Manufacturer: VISHAY DALE; Manufacturer Part Number: CRCW04020000Z0ED; No_Mount: NM; PART_NUMBER: C17927-001; PATH: I167; PHYS_PAGE: 9; Part Number: RK73Z1ETTP; TOLERANCE: 0; WATTAGE: 1/20W; XY: (-2000,4825)
R2L1 = RESN#1: RES SMD 0.0OHM JUMPER 1/16W 0402; MFG: KOA SPEER; MFG_PN: RK73Z1ETTP; Manufacturer: VISHAY DALE; Manufacturer Part Number: CRCW04020000Z0ED; PART_NUMBER: C17927-001; PATH: I26; PHYS_PAGE: 35; Part Number: ERJ-2GE0R00X; TOLERANCE: 0; WATTAGE: 1/10W; XY: (-5325,1400)
R3A1 R3A2 = RESN: RES SMD 200 OHM 1% 1/16W 0402; MFG: KOA SPEER; MFG_PN: RK73B1ETTP331J; Manufacturer: VISHAY DALE; Manufacturer Part Number: CRCW0402200RFKED; No_Mount: NM; PART_NUMBER: A93549-012; PATH: I20; PHYS_PAGE: 35; Part Number: RK73B1ETTP331J; TOLERANCE: 1%; WATTAGE: 1/16W; XY: (-3825,2000)
R644 R647 R651 R656-R658 R661 R665 R763 R908 R912 = RESISTOR_2: RES 10K OHM 1/10W 5% 0402 SMD; Manufacturer: Panasonic Electronic Components; Part Number: ERJ-2GEJ103X; TOLERANCE: 5%; WATTAGE: 1/10W
R645 R648 R650 R659 R662 R918 R919 = RES_1.0_OHM_1_16W_0402_SMD: RES SMD 0.0OHM JUMPER 1/16W 0402; MATERIAL: ?; Manufacturer: VISHAY DALE; Manufacturer Part Number: CRCW04020000Z0ED; Part Number: ERJ-2GE0R00X; TOLERANCE: ?; Wattage: 1/10W
R646 R660 = 100K-1_16W-5%-0603_0: RES 100K OHM 1/10W 5% 0402 SMD; Manufacturer: VISHAY DALE; Manufacturer Part Number: CRCW0402100KJNED; Part Number: ERJ-2GEJ104X; TOLERANCE: 5%; Wattage: 1/10W
R649 R652 R666 = RESISTOR_1: RES SMD 4.7K OHM 5% 1/16W 0402; Manufacturer: Panasonic; Manufacturer Part Number: ERJ-2GEJ472X; Tolerance: ±5%; Wattage: 1/16W
R653 R655 = RES_1.0_OHM_1_16W_0402_SMD: RES SMD 10 OHM 1% 1/10W 0402; MATERIAL: ?; Manufacturer: Panasonic Electronic Components; Part Number: ERJ-2RKF10R0X; TOLERANCE: 1%; Wattage: 1/10W
R654 = RES_0.9_OHM_1_10W_1%_0402_SMD: RES SMD 0.002 OHM 1% 2W 2512; Manufacturer: Stackpole Electronics Inc; Manufacturer Part Number: CSNL2512FT2L00; Part Number: CSNL2512FT2L00; TOLERANCE: 1%; WATTAGE: 2W
U3B1 = TPS22922: IC LOAD SWITCH 1CH 6DSBGA; MATERIAL: IC; MFG: TEXAS INSTRUMENTS; MFG_PN: TPS22922YZPR; Manufacturer: TEXAS INSTRUMENTS; PART_NUMBER: E64793-001; PATH: I101; PHYS_PAGE: 50; XY: -3,425,900
U72 = INA226_6: IC MONITOR PWR/CURR BIDIR 10MSOP; Manufacturer: Texas Instruments; Manufacturer Part Number: INA226AIDGSR; Part Number: INA226AIDGSR
A4 = 4-881545-2_1: ROUND STANDOFF M2 STEEL 3MM; Alt.Part Number: 4-881545-2; Manufacturer: Wurth Electronics Inc
C3A2 = CAP_CER_0.1UF_10V_10%_X5R_0402: CAP CER 10UF 10V X7T 0603; MATERIAL: X7R; Manufacturer: Samsung Electro-Mechanics America, Inc.; PART_NUMBER: 0.1UF; Part Number: CL05A106MQ5NUNC; TOLERANCE: 10%; VOLTAGE: 10V
C790 = CAP_CER_0.1UF_10V_10%_X5R_0402: CAP CER 10000PF 50V X7R 0402; MATERIAL: X7R; Manufacturer: Murata Electronics North America; Manufacturer Part Number: GRM155R71H103KA88D; PART_NUMBER: 0.1UF; Part Number: GRM155R71H103KA88D; TOLERANCE: 10%; VOLTAGE: 50V
R663 = RESISTOR_1: RES 4.7K OHM 1/10W 5% 0402 SMD; Manufacturer: Panasonic; Manufacturer Part Number: ERJ-2GEJ472X; Tolerance: ±5%; Wattage: 1/16W
R664 = RES_1.0_OHM_1_16W_0402_SMD: RES 0.0 OHM 1/10W JUMP 0402 SMD; MATERIAL: ?; Manufacturer: VISHAY DALE; Manufacturer Part Number: CRCW04020000Z0ED; Part Number: ERJ-2GE0R00X; TOLERANCE: ?; Wattage: 1/10W
C795 C797 C802 C803 C828 = CAP_CER_0.1UF_10V_10%_X5R_0402: CAP CER 10UF 25V 10% X7R 1206; MATERIAL: X7R; Manufacturer: Taiyo Yuden; PART_NUMBER: 0.1UF; Part Number: TMK316B7106KL-TD; TOLERANCE: 10%; VOLTAGE: 25V
C807 C811 C825 C826 = cap_0402_1uF_10V_10%_X5R_smd
C808 C812 = CAP: CAP CER 470PF 50V X5R 0402; Assembly Option: LOAD; Manufacturer: TDK Corporation; Manufacturer PN: CGA2B2X5R1H471K050BA; Manufacturer Part Number: CGA2B2X5R1H471K050BA; Operating Temperature Maximum: 85 C; Operating Temperature Minimum: -55 C; PART_NUMBER: PAC_CAP_02528; Package Size: 0402; Temperature Coefficient: X5R; Tolerance: 10%; Datasheet: https://product.tdk.com/info/en/catalog/datasheets/mlcc_commercial_general_en.pdf
D25-D27 = LED: LED RED DIFFUSED 0603 SMD; Manufacturer: Lumex; Manufacturer Part Number: SML-LX0603IW-TR
FB20-FB24 = FB_0: FERRITE CHIP 120 OHM 2000MA 0603; Current: 2A; Manufacturer: Murata Electronics North America; Manufacturer Part Number: BLM18PG121SN1D; Part Number: BLM18PG121SN1D
J23 J24 = CON_RF_3PIN: CONN UMC JACK STR 50 OHM SMD; Manufacturer: Hirose Electric Co Ltd; Manufacturer Part Number: U.FL-R-SMT; Mfgr: Hirose Electric Co Ltd; Part Number: U.FL-R-SMT
R667-R669 R671-R674 R680-R692 R696 R697 R699-R701 R705 R711-R714 R718-R721 R727-R730 R739-R742 R749 R750 R776 R782 R866 R922-R924 = RESISTOR_1: RES SMD 10K OHM 5% 1/16W 0402; Manufacturer: VISHAY DALE; Manufacturer Part Number: CRCW040210K0JNED; Tolerance: ±5%; Wattage: 1/16W
R670 = res_0402_0R0_0.1W_Jmpr_smd: RES SMD 0.0OHM JUMPER 1/16W 0402; Manufacturer: VISHAY DALE; Manufacturer Part Number: CRCW04020000Z0ED; Tolerance: jmpr
R675-R677 = RESISTOR_3: RES SMD 200 OHM 1% 1/16W 0402; Manufacture: YAGEO; ManufacturePN: RC0402FR-07300RL; Manufacturer: VISHAY DALE; Manufacturer Part Number: CRCW0402200RFKED; Part Number: 107B2130001D; Tolerance: 1%
R678 R679 = res_0402_220R0_0.063W_1%_smd: Manufacturer: VISHAY DALE; Manufacturer Part Number: CRCW0402220RFKED
R752-R757 R777-R780 R786 = RESISTOR_1: RES SMD 22 OHM 1% 1/16W 0402; MFG: VISHAY DALE; MFG_PN: CRCW040222R0FKED; Manufacturer: VISHAY DALE; Manufacturer Part Number: CRCW040222R0FKED; Tolerance: ±1%; Wattage: 1/16W
R882 = R: RES SMD 0 OHM 1W 1812 WIDE; Manufacturer: Vishay Dale; Manufacturer Part Number: RCL12180000Z0EK
TP64-TP70 = T_POINT_R
U73 = TTETALSANF-25.000000: Manufacturer: Taitien
U74 = IDT82P33913-1: Synchronization Management Unit; Manufacturer: IDT
U75 = SN74LVC3G34: Manufacturer: Texas Instruments; Manufacturer Part Number: SN74LVC3G34DCUR
U76 = TLV70018DDCT: IC REG LINEAR 1.8V 200MA SOT23-5; Manufacturer: Texas Instruments
C832-C834 C849 C906 = cap_0402_0.1uF_16V_10%_X7R: CAP CER 0.1UF 25V 10% X7R 0402; Manufacturer: MURATA; Manufacturer Part Number: GRM155R71C104KA88D; Voltage: 25V
C883 = CAP_NONPOL: CAP CER 0.1UF 25V 10% X7R 0402; MFG: Murata; MFG_PN: GRM155R71C104KA88D; Manufacturer: MURATA; Manufacturer Part Number: GRM155R71C104KA88D; Tolerance: ±10%; Voltage: 25V
C884 = cap_0603_22uF_6V3_10%_X5R: MFG: Murata; MFG_PN: GRM187R60J226ME15D; Manufacturer: MURATA; Manufacturer Part Number: GRM187R60J226ME15D
D28 = SFH_4059-RS
JP2 = Header_1X2: Manufacturer: Samtec; Part Number: TSW-102-07-T-S
R128 R129 R132 R133 = RESISTOR_1: RES SMD 10K OHM 5% 1/16W 0402; MFG: VISHAY DALE; MFG_PN: CRCW040210K0JNED; Manufacturer: VISHAY DALE; Manufacturer Part Number: CRCW040210K0JNED; Tolerance: ±5%; Wattage: 1/16W
U8 U77-U79 U81 = SE98ATP,547_1: IC TEMP SENSOR DDR 8-HWSON; Manufacturer: NXP Semiconductors
U88 = Si1141
R706-R710 R715-R717 R736-R738 R743 R764-R766 = RES_0: RES SMD 0.0OHM JUMPER 1/16W 0402; Assembly Option: LOAD; Manex: 101-0000554; Manufacturer: VISHAY DALE; Manufacturer Part Number: CRCW04020000Z0ED; Operating Temperature Maximum: -55C - 155C; Operating Temperature Minimum: -55C - 155C; PART_NUMBER: PAC_RES_02050; Package Size: 0402; Rated Power: 1/10W; Temperature Coefficient: 100ppm/C; Datasheet: http://industrial.panasonic.com/www-cgi/jvcr13pz.cgi?E+PZ+3+AOA0002+ERJ2RKF1002X+7+WW
R722 R723 R725 R731-R734 R745-R748 = RES: RES SMD 1K OHM 5% 1/16W 0402; Manufacture: YAGEO; ManufacturePN: RC0402JR-071K5L; Manufacturer: VISHAY DALE; Manufacturer Part Number: CRCW04021K00JNED; Part Number: 107B2115011D; Tolerance: ±5%; WATTAGE: 1/16W
R724 R744 = R_1: RES SMD 121 OHM 1% 1/16W 0402; Manufacturer: Yageo; Manufacturer Part Number: RC0402FR-07121RL; Part Number: RC0402FR-07121RL; TOLERANCE: 1%; WATTAGE: 1/16W
R726 = RES: RES SMD 1K OHM 5% 1/16W 0402; MFG: YAGEO; MFG_PN: RC0402JR-071K5L; Manufacture: YAGEO; ManufacturePN: RC0402JR-071K5L; Manufacturer: VISHAY DALE; Manufacturer Part Number: CRCW04021K00JNED; Part Number: 107B2115011D; Tolerance: ±5%; WATTAGE: 1/16W
R735 R751 = RESISTOR_1: RES SMD 100K OHM 5% 1/16W 0402; Manufacturer: VISHAY DALE; Manufacturer Part Number: CRCW0402100KJNED; Tolerance: ±5%; Wattage: 1/16W
U82-U84 = SN74AVC4T774RGYR_2: IC BUS TRANSCVR 4BIT DUAL 16QFN; Manufacturer: Texas Instruments
U95 = PCA9517A: CDS_LIB: lf_digital; CDS_LOCATION: U4D1; CDS_PART_NAME: PCA9517A_TSSOPLF-E37094-001-SSOP8_65MM_3W; CDS_SEC: 1; DRAWING: @VALLEY_ISLAND_LIB.VALLEY_ISLAND(SCH_1):PAGE44; LOCATION: U4D1; MATERIAL: IC; MFG: NXP SEMICONDUCTORS; MFG_PN: PCA9517ADP; Manufacturer: NXP SEMICONDUCTORS; PACK_TYPE: TSSOPLF; PART_NUMBER: E37094-001; PATH: I66; PHYS_PAGE: 17; Part Number: PCA9517ADP; ROT: 0; SEC: 1; VER: 2; XY: (-2225,3750)
C1N1 C903-C905 = cap_0402_0.1uF_16V_10%_X7R: CAP CER 0.1UF 25V 10% X7R 0402; MATERIAL: X7R; MFG: TAIYO; MFG_PN: TMK105BJ104KV-F; Manufacturer: MURATA; Manufacturer Part Number: GRM155R71C104KA88D; PART_NUMBER: G41157-001; PATH: I128; PHYS_PAGE: 25; Part Number: C1005X7R1E104K050BB; TOLERANCE: 10%; VOLTAGE: 25V; XY: (-4725,3525)
R759 = RESISTOR_0: RES 10K OHM 1/10W 5% 0402 SMD; Manufacturer: Panasonic Electronic Components; Part Number: ERJ-2GEJ103X; TOLERANCE: 5%; WATTAGE: 1/10W
R761 = R_1: RES 10K OHM 1/10W 5% 0402 SMD; Manufacturer: Panasonic Electronic Components; Part Number: ERJ-2GEJ103X; TOLERANCE: 5%; WATTAGE: 1/10W
U85 = TS3A27518ERTWR: IC MUX/DEMUX 6X1 24WQFN; Manufacturer: Texas Instruments
U86 = SLB9645VQ1_1.2: Manufacturer Part Number: SLB9645XQ1_2

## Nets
GND: C1N1.2 C3A1.2(B[0]) C3A2.2(B[0]) C3B1.1 C3B2.2 C3B3.2 C3L1.2(B[0]) C3L2.2(B[0]) C3N1.2 C3N2.2 C781.2(B[0]) C784.1(A[0]) C788.2(B[0]) C791.2(B[0]) C792.2(B[0]) C793.2(B[0]) C794.2(B[0]) C795.2(B[0]) C796.2(B[0]) C797.2(B[0]) C798.2(B[0]) C799.2(B[0]) C800.2(B[0]) C801.2(B[0]) C802.2(B[0]) C803.2(B[0]) C804.2(B[0]) C805.2(B[0]) C806.2(B[0]) C807.2 C808.2 C809.2(B[0]) C810.2(B[0]) C811.2 C812.2 C813.2(B[0]) C814.2(B[0]) C815.2(B[0]) C816.2(B[0]) C817.2(B[0]) C818.2(B[0]) C819.2(B[0]) C820.2(B[0]) C821.2(B[0]) C822.2(B[0]) C823.2(B[0]) C824.2(B[0]) C825.2 C826.2 C827.2(B[0]) C828.2(B[0]) C829.2(B[0]) C830.2(B[0]) C831.2(B[0]) C832.2 C833.2 C834.2 C835.2(B[0]) C836.2(B[0]) C837.2(B[0]) C838.2(B[0]) C839.2(B[0]) C840.2(B[0]) C841.2(B[0]) C842.2(B[0]) C849.2 C883.2 C884.1 C903.2 C904.2 C905.2 C906.2 C914.1(A[0]) C915.1(A[0]) D25.C D26.C D27.C J3M1.4(GND) J3M1.9(GND) J3M1.15(GND) J3M1.18(GND) J3M1.21(GND) J3M1.26(GND) J3M1.27(GND) J3M1.29(GND) J3M1.34(GND) J3M1.35(GND) J3M1.37(GND) J3M1.40(GND) J3M1.43(GND) J3M1.50(GND) J3M1.MP1 J3M1.MP2 J3M2.4(GND) J3M2.9(GND) J3M2.15(GND) J3M2.18(GND) J3M2.21(GND) J3M2.26(GND) J3M2.27(GND) J3M2.29(GND) J3M2.34(GND) J3M2.35(GND) J3M2.37(GND) J3M2.40(GND) J3M2.43(GND) J3M2.50(GND) J3M2.MP1 J3M2.MP2 J23.2 J23.3 J24.2 J24.3 JP2.2 Q3A1.1(S1) Q3A1.4(S2) Q3A2.1(S1) Q3A2.4(S2) Q9.2(S) Q10.2(S) Q11.2(S) Q12.2(S) R2B1.2(B[0]) R2B2.2(B[0]) R132.1 R133.1 R646.1(A[0]) R660.1(A[0]) R672.2 R673.2 R674.2 R681.2 R682.2 R686.1 R687.1 R688.1 R689.1 R690.1 R696.1 R697.1 R705.1 R722.1(Pin1) R723.1(Pin1) R725.1(Pin1) R726.1(Pin1) R728.1 R729.1 R730.1 R731.1(Pin1) R732.1(Pin1) R733.1(Pin1) R734.1(Pin1) R735.1 R745.1(Pin1) R746.1(Pin1) R747.1(Pin1) R748.1(Pin1) R750.1 R751.1 R759.1 R761.2(B[0]) R766.1 R776.2 R912.2 U3B1.C1(GND) U8.4(VSS) U8.9(TP) U72.7(GND) U73.2(GND) U74.19(VSSAO1) U74.23(VSSAO2) U74.47(SDI/I2C_AD2/UART_RX) U74.49(CS/I2C_AD0) U74.73(VSS_EP) U75.4(GND) U76.2(GND) U77.4(VSS) U77.9(TP) U78.4(VSS) U78.9(TP) U79.4(VSS) U79.9(TP) U81.4(VSS) U81.9(TP) U82.10(GND) U82.17(PAD) U83.10(GND) U83.17(PAD) U84.10(GND) U84.17(PAD) U85.2(GND) U85.25(PAD) U86.16(GND1) U86.26(GND2) U86.32(GND3) U86.33(EP) U88.8(GND) U95.4(GND) ; also on sheet 1 2 10 11 12 13 14 15 16 17 18 19 20 21 22 23 24 25 26 27 28 29 30 31 32 33 34 35 36 37 38 39 40 41 42 49 50 51 52 53 54
V3P3: C791.1(A[0]) C792.1(A[0]) C798.1(A[0]) C800.1(A[0]) C825.1 FB20.2 FB21.2 FB22.2 FB23.2 R653.2(B[0]) R654.1(A[0]) R656.1 R657.1 U76.1(IN) U76.3(EN) ; also on sheet 10 11 12 14 17 18 22 24 25 26 27 29 30 31 32 33 34 35 49 51 53 54
V3P3_TIVA: C1N1.1 C883.1 C903.1 C904.1 C905.1 R763.2 R765.2 R786.1 R866.2 U85.5(VCC) U86.1(VDD1) U86.9(VDD2) U86.10(VDD3) U88.3(VDD) U88.6(LED2/CVDD) U88.7(LED3/CVDD) ; also on sheet 37 38 39 40 41 42
V3P3_TIVA_LT: C784.2(B[0]) C832.1 C833.1 C834.1 C835.1(A[0]) C837.1(A[0]) C840.1(A[0]) C849.1 C906.1 C915.2(B[0]) R128.2 R129.2 R644.2 R658.2 R683.2 R684.2 R685.2 R691.2 R692.2 R699.2 R700.2 R701.2 R711.2 R712.2 R713.2 R714.2 R718.2 R719.2 R720.2 R721.2 R727.2 R739.2 R740.2 R741.2 R742.2 R749.2 R908.1 R922.2 U8.8(VDD) U72.6(VS) U77.8(VDD) U78.8(VDD) U79.8(VDD) U81.8(VDD) U82.16(VCCA) U83.16(VCCA) U84.16(VCCA) U95.1(VCCA) ; also on sheet 1 2 19 20 21 28 29 31 37 38 39 40 42 52 54
V3P3_TRXFE: C836.1(A[0]) C838.1(A[0]) C841.1(A[0]) C914.2(B[0]) R923.2 R924.2 U82.15(VCCB) U83.15(VCCB) U84.15(VCCB) U95.8(VCCB) ; also on sheet 42
VDD_V3P3: C794.1(A[0]) C795.1(A[0]) C805.1(A[0]) C806.1(A[0]) FB20.1 U74.40(VDD1) U74.62(VDD2)
VDDA_V3P3: C796.1(A[0]) C797.1(A[0]) C813.1(A[0]) C814.1(A[0]) C815.1(A[0]) C816.1(A[0]) C817.1(A[0]) C818.1(A[0]) C819.1(A[0]) C820.1(A[0]) FB21.1 U74.2(VDDA1) U74.3(VDDA2) U74.4(VDDA3) U74.5(VDDA4) U74.10(VDDA5) U74.11(VDDA6) U74.12(VDDA7)
VDDAO_V3P3: C799.1(A[0]) C803.1(A[0]) C821.1(A[0]) C822.1(A[0]) C823.1(A[0]) C824.1(A[0]) FB22.1 U74.20(VDDAO1) U74.24(VDDAO2) U74.69(VDDAO3) U74.72(VDDAO4)
VDDO_V3P3: C793.1(A[0]) C801.1(A[0]) C802.1(A[0]) C804.1(A[0]) C829.1(A[0]) C830.1(A[0]) C831.1(A[0]) FB23.1 R667.1 R668.1 R669.1 R671.1 R680.1 R782.2 U73.4(VDD) U74.27(VDDO1) U74.29(VDDO2) U74.64(VDDO3) U74.66(VDDO4) U75.8(VCC)
ETHSW_SYNCLK_OUT: U74.41(IN6) ; also on sheet 19
ETHSW_TEMP_EVENT: R701.1 U81.7(NEVENT) ; also on sheet 1
I2C2_SCLK_MUX: R756.1 U85.22(NC2)
I2C2_SDA_MUX: R755.1 U85.23(NC1)
IDT_1P8: FB24.2 R882.2
IDT_1P8_LDO: C826.1 R882.1 U76.5(OUT)
IDT_1588_1PPS_IN: U74.37(IN5) ; also on sheet 10
IDT_1588_1PPS_OUT: R778.1 ; also on sheet 10
IDT_1588_CLK_OUT: R779.1 ; also on sheet 10
IDT_INT_REQ: R782.1 U74.57(INT_REQ) ; also on sheet 53
IDT_JTAG_TCK: TP68.1(TP) U74.16(TCK)
IDT_JTAG_TDI: TP67.1(TP) U74.17(TDI)
IDT_JTAG_TDO: TP66.1(TP) U74.18(TDO)
IDT_JTAG_TMS: TP70.1(TP) U74.14(TMS)
IDT_JTAG_TRSTB: R776.1 TP69.1(TP) U74.15(TRSTB)
IDT_OSCI: R777.1 U74.6(OSCI)
IDT_VDD_1P8: C809.1(A[0]) C810.1(A[0]) C827.1(A[0]) C828.1(A[0]) FB24.1 U74.42(VDD1V8_1) U74.53(VDD1V8_2)
ISO_SOC_TRXFE_GPIO1: R706.2 ; also on sheet 42
ISO_SOC_TRXFE_GPIO2: R707.2 ; also on sheet 42
ISO_SOC_TRXFE_GPIO3: R708.2 ; also on sheet 42
ISO_SOC_TRXFE_GPIO4: R715.2 ; also on sheet 42
ISO_SOC_TRXFE_GPIO5: R716.2 ; also on sheet 42
ISO_SOC_TRXFE_GPIO6: R717.2 ; also on sheet 42
ISO_TIVA_TRXFECONN_GPIO1: R736.2 ; also on sheet 42
ISO_TIVA_TRXFECONN_GPIO2: R737.2 ; also on sheet 42
ISO_TIVA_TRXFECONN_GPIO3: R738.2 ; also on sheet 42
L_SATA0_RXN: C783.1(A[0]) J3M1.23(PERN0)
L_SATA0_RXP: C782.1(A[0]) J3M1.25(PERP0)
L_SATA0_TXN: C780.1(A[0]) J3M1.31(PETN0)
L_SATA0_TXP: C779.1(A[0]) J3M1.33(PETP0)
L_TIVA_TRXFECONN_I2C2_SCLK: R924.1 U95.7(SCLB) ; also on sheet 42
L_TIVA_TRXFECONN_I2C2_SDA: R923.1 U95.6(SDAB) ; also on sheet 42
L_TRXFE_RESET: R743.2 ; also on sheet 42
LED_TEMP_EVENT: R685.1 U78.7(NEVENT) ; also on sheet 1
LIGHT_SENSE_INT: JP2.1 R866.1 U88.4(INT) ; also on sheet 37
MEM_RESET_L: R648.1(A[0]) R662.1(A[0]) R670.2 ; also on sheet 22 32 49
MSATA0_DAS: C781.1(A[0]) Q9.1(G) R646.2(B[0]) R650.1(A[0]) R918.1(A[0])
MSATA0_RESET: J3M1.22(PERST_N) R647.1 R648.2(B[0])
MSATA0_TIVA_DAS: R645.2(B[0]) ; also on sheet 37
MSATA1_DAS: C788.1(A[0]) Q10.1(G) R660.2(B[0]) R664.1(A[0]) R919.1(A[0])
MSATA1_RESET: J3M2.22(PERST_N) R661.1 R662.2(B[0])
MSATA1_TIVA_DAS: R659.2(B[0]) ; also on sheet 37
MSATA_PWR_EN: R2L1.1(A[0]) ; also on sheet 37
MSATA_V3P3: C3A1.1(A[0]) C3A2.1(A[0]) C3B2.1 C3B3.1 C3L1.1(A[0]) C3L2.1(A[0]) C3N1.1 C3N2.1 J3M1.2(3P3V_AUX) J3M1.24(3P3V_AUX) J3M1.39(3P3V_AUX) J3M1.41(3P3V_AUX) J3M1.52(3P3V_AUX) J3M2.2(3P3V_AUX) J3M2.24(3P3V_AUX) J3M2.39(3P3V_AUX) J3M2.41(3P3V_AUX) J3M2.52(3P3V_AUX) R3A1.1(A[0]) R3A2.1(A[0]) R647.2 R649.2 R651.1 R652.2 R661.2 R663.2 R665.1 R666.2 U3B1.A1(VOUT1) U3B1.B1(VOUT2)
MSATA_V3P3_CM: C3B1.2 R654.2(B[0]) R655.2(B[0]) U3B1.A2(VIN1) U3B1.B2(VIN2) U72.8(VBUS)
OCT_TEMP_EVENT: R129.1 U8.7(NEVENT) ; also on sheet 1
OCT_TWS0_SCL: U74.50(SCLK/I2C_SCL) ; also on sheet 53
OCT_TWS0_SDA: U74.51(SDO/I2C_SDA/UART_TX) ; also on sheet 53
OCT_TWS1_SCL: R754.2 ; also on sheet 11 18 26 27 52 53
OCT_TWS1_SDA: R753.2 ; also on sheet 11 18 26 27 52 53
OUT3_N: J23.1 U74.26(OUT3_NEG)
OUT3_P: J24.1 U74.25(OUT3_POS)
POWER_TEMP_EVENT0: R683.1 U77.7(NEVENT) ; also on sheet 1
POWER_TEMP_EVENT1: R692.1 U79.7(NEVENT) ; also on sheet 1
RESV: J3M1.51(RESERVED) R2B1.1(A[0])
RESV0: J3M1.49(RESERVED) R650.2(B[0])
RST_IDT: R670.1 U74.52(RSTB)
SATA0_LED_L: Q3A1.5(G2) Q3A1.6(D1) R649.1
SATA0_RX_N: C783.2(B[0]) ; also on sheet 50
SATA0_RX_P: C782.2(B[0]) ; also on sheet 50
SATA0_TX_N: C780.2(B[0]) ; also on sheet 50
SATA0_TX_P: C779.2(B[0]) ; also on sheet 50
SATA1_RX_N: C790.2(B[0]) ; also on sheet 50
SATA1_RX_P: C789.2(B[0]) ; also on sheet 50
SATA1_TX_N: C787.2(B[0]) ; also on sheet 50
SATA1_TX_P: C786.2(B[0]) ; also on sheet 50
SATA_PWR_ALERT: R908.2 U72.3(ALERT) ; also on sheet 37
SOC_TRXFE_GPIO1: U82.3(A1) ; also on sheet 10
SOC_TRXFE_GPIO2: U82.4(A2) ; also on sheet 10
SOC_TRXFE_GPIO3: U82.5(A3) ; also on sheet 10
SOC_TRXFE_GPIO4: U82.6(A4) ; also on sheet 10
SOC_TRXFE_GPIO5: R709.1 ; also on sheet 10
SOC_TRXFE_GPIO6: R710.1 ; also on sheet 10
SYNCE_CLK: R780.1 ; also on sheet 19
TIVA_PSE_I2C8_SCLK: U78.6(SCL) U88.2(SCL) ; also on sheet 37 41 42
TIVA_PSE_I2C8_SDA: U78.5(SDA) U88.1(SDA) ; also on sheet 37 41 42
TIVA_PWRMNTR_I2C6_SCLK: U72.5(SCL) ; also on sheet 1 28 29 31 37 38
TIVA_PWRMNTR_I2C6_SDA: U72.4(SDA) ; also on sheet 1 28 29 31 37 38
TIVA_RESET: R764.2 ; also on sheet 1 38 40
TIVA_TEMPSEN_I2C1_SCLK: U8.6(SCL) U77.6(SCL) U79.6(SCL) U81.6(SCL) ; also on sheet 37
TIVA_TEMPSEN_I2C1_SDA: U8.5(SDA) U77.5(SDA) U79.5(SDA) U81.5(SDA) ; also on sheet 37
TIVA_TRXFECONN_GPIO1: U84.3(A1) ; also on sheet 37
TIVA_TRXFECONN_GPIO2: U84.4(A2) ; also on sheet 37
TIVA_TRXFECONN_GPIO3: U84.5(A3) ; also on sheet 37
TIVA_TRXFECONN_I2C2_SCLK: R756.2 U95.2(SCLA) ; also on sheet 37
TIVA_TRXFECONN_I2C2_SDA: R755.2 U95.3(SDAA) ; also on sheet 37
TP_2K_1PPS: TP64.1(TP) U74.44(MFRSYNC_2K_1PPS)
TP_8K_1PPS: TP65.1(TP) U74.43(FRSYNC_8K_1PPS)
TPM_DATA: R752.1 U86.29(SDA)
TPM_I2C_MUX_SEL: R759.2 U85.11(IN2) U85.21(IN1) ; also on sheet 37
TPM_INT_REQ: R763.1 U86.2(DAVINT#) ; also on sheet 37
TPM_PP: R765.1 R766.2 U86.31(PP)
TPM_RESETn: R764.1 U86.8(RESET#)
TPM_SCLK: R757.1 U86.30(SCL)
TRXFE_12V_ONOFF: C839.1(A[0]) C842.1(A[0]) Q11.1(G) Q12.1(G) R735.2 R751.2 ; also on sheet 31 37
TRXFE_ISO_EN: R724.1(A[0]) U82.9(NOE) U83.9(NOE)
TRXFE_RESET: U84.6(A4) ; also on sheet 40
TWS1_SCLK_MUX: R754.1 U85.10(NO2)
TWS1_SDA_MUX: R753.1 U85.8(NO1)
UNNAMED_57_CAPN_I137_A: C786.1(A[0]) J3M2.33(PETP0)
UNNAMED_57_CAPN_I141_A: C787.1(A[0]) J3M2.31(PETN0)
UNNAMED_57_CAPN_I158_A: C789.1(A[0]) J3M2.25(PERP0)
UNNAMED_57_MPCIE52PNUTSKITGI_I160_RESERVED51: J3M2.51(RESERVED) R2B2.1(A[0])
UNNAMED_247_MOSFETNDUAL6P_I21_D1: Q3A2.5(G2) Q3A2.6(D1) R663.1
UNNAMED_247_MOSFETNDUAL6P_I21_G1: Q3A1.2(G1) R651.2 R918.2(B[0])
UNNAMED_247_MOSFETNDUAL6P_I21_G1 (page 48. mSATA CONNECTOR1): Q3A2.2(G1) R665.2 R919.2(B[0])
N20742573: C785.1(A[0]) R653.1(A[0]) U72.10(IN+)
N20742575: C785.2(B[0]) R655.1(A[0]) U72.9(IN-)
N20742856: R656.2 U72.2(A0)
N20742859: R657.2 U72.1(A1)
N20870118: Q9.3(D) R644.1 R645.1(A[0])
N25801615: R2L1.2(B[0]) R912.1 U3B1.C2(ON)
N25802251: D23.K Q3A1.3(D2) R652.1
N25802267: D23.A R3A1.2(B[0])
N31005584: C790.1(A[0]) J3M2.23(PERN0)
N31005652: Q10.3(D) R658.1 R659.1(A[0])
N31005658: J3M2.49(RESERVED) R664.2(B[0])
N31005696: D24.K Q3A2.3(D2) R666.1
N31005704: D24.A R3A2.2(B[0])
N31056057: R761.1(A[0]) U85.17(NEN)
N31056144: R752.2 U85.1(COM1)
N31056146: R757.2 U85.3(COM2)
N31142043: C812.1 R679.1 U74.1(VC2)
N31142128: C807.1 R678.2
N31142226: C811.1 R679.2
N31142286: C808.1 R678.1 U74.13(VC1)
N31180884: R671.2 R672.1 U74.7(XO_FREQ0/LOS0)
N31180935: R668.2 R673.1 U74.8(XO_FREQ1/LOS1)
N31181028: R669.2 R674.1 U74.9(XO_FREQ2/LOS2)
N31181939: R667.2 U74.58(MS/SL)
N31182714: R681.1 U74.46(MPU_MODE1/I2CM_SCL)
N31182719: R682.1 U74.45(MPU_MODE0/I2CM_SDA)
N31183857: R680.2 U74.48(CLKE/I2C_AD1)
N31184017: R779.2 U74.28(OUT2)
N31184020: R778.2 U74.30(OUT1)
N31184143: R777.2 U73.3(OUT)
N31185504: U74.55(DPLL1_LOCK) U75.1(1A)
N31185513: U74.56(DPLL2_LOCK) U75.3(2A)
N31185522: U74.54(DPLL3_LOCK) U75.6(3A)
N31185623: R675.2 U75.7(1Y)
N31185626: R677.2 U75.2(3Y)
N31645451: R686.2 U77.3(A2)
N31645457: R687.2 U77.2(A1)
N31645461: R688.2 U77.1(A0)
N31645826: R696.2 U79.3(A2)
N31645842: R697.2 U79.2(A1)
N31645846: R691.1 U79.1(A0)
N31646435: R705.2 U81.3(A2)
N31646451: R700.1 U81.2(A1)
N31646455: R699.1 U81.1(A0)
N31647946: R689.2 U78.3(A2)
N31647952: R684.1 U78.2(A1)
N31647956: R690.2 U78.1(A0)
N31820809: R706.1 U82.14(B1)
N31820811: R707.1 U82.13(B2)
N31820813: R708.1 U82.12(B3)
N31820815: R715.1 U82.11(B4)
N31820857: R712.1 R723.2(Pin2) U82.2(DIR2)
N31820861: R713.1 R725.2(Pin2) U82.7(DIR3)
N31820881: R711.1 R722.2(Pin2) U82.1(DIR1)
N31820905: R714.1 R726.2(Pin2) U82.8(DIR4)
N31820936: Q11.3(D) R724.2(B[0]) R727.1 R730.2
N31821289: R716.1 U83.14(B1)
N31821291: R717.1 U83.13(B2)
N31821345: R718.1 R731.2(Pin2) U83.1(DIR1)
N31821353: R719.1 R732.2(Pin2) U83.2(DIR2)
N31821357: R720.1 R733.2(Pin2) U83.7(DIR3)
N31821369: R721.1 R734.2(Pin2) U83.8(DIR4)
N31821638: R728.2 U83.5(A3)
N31821642: R729.2 U83.6(A4)
N31822857: R736.1 U84.14(B1)
N31822859: R738.1 U84.12(B3)
N31822861: R737.1 U84.13(B2)
N31822881: R743.1 U84.11(B4)
N31823115: Q12.3(D) R744.2(B[0]) R749.1 R750.2
N31823212: R744.1(A[0]) U84.9(NOE)
N31823252: R739.1 R745.2(Pin2) U84.1(DIR1)
N31823260: R740.1 R746.2(Pin2) U84.2(DIR2)
N31823268: R741.1 R747.2(Pin2) U84.7(DIR3)
N31823276: R742.1 R748.2(Pin2) U84.8(DIR4)
N31826578: R709.2 U83.3(A1)
N31826605: R710.2 U83.4(A2)
N32609403: R780.2 U74.65(OUT7)
N33210469: D28.1(cathode) U88.9(LED1)
N33210482: C884.2 D28.2(anode) R786.2
N33222661: R132.2 U8.3(A2)
N33222667: R128.1 U8.2(A1)
N33222669: R133.2 U8.1(A0)
N33738427: R922.1 U95.5(EN)
N34187930: D25.A R675.1
N34187931: R676.2 U75.5(2Y)
N34187932: D26.A R676.1
N34187933: D27.A R677.1

Not connected (* = marked no-connect by the designer): A2 1; A4 1; J3M1 1(WAKE_N) 3(COEX1) 5(COEX2) 6(1P5V)* 7(CLKREQ_N) 8(UIM_PWR) 10(UIM_DATA) 11(REFCLK_M) 12(UIM_CLK) 13(REFCLK_P) 14(UIM_RESET) 16(UIM_VPP) 17(RESERVED) 19(RESERVED) 20(W_DISABLE_N) 28(1P5V)* 30(SMB_CLK) 32(SMB_DATA) 36(USB_D_M) 38(USB_D_P) 42(LED_WWAN_N) 44(LED_WLAN_N) 45(RESERVED) 46(LED_WPAN_N) 47(RESERVED) 48(1P5V)*; J3M2 1(WAKE_N) 3(COEX1) 5(COEX2) 6(1P5V)* 7(CLKREQ_N) 8(UIM_PWR) 10(UIM_DATA) 11(REFCLK_M) 12(UIM_CLK) 13(REFCLK_P) 14(UIM_RESET) 16(UIM_VPP) 17(RESERVED) 19(RESERVED) 20(W_DISABLE_N) 28(1P5V)* 30(SMB_CLK) 32(SMB_DATA) 36(USB_D_M) 38(USB_D_P) 42(LED_WWAN_N) 44(LED_WLAN_N) 45(RESERVED) 46(LED_WPAN_N) 47(RESERVED) 48(1P5V)*; U73 1(NC)*; U74 21(OUT4_POS) 22(OUT4_NEG) 31(IN1_POS) 32(IN1_NEG) 33(IN2_POS) 34(IN2_NEG) 35(IN3_POS) 36(IN3_NEG) 38(IN4_POS) 39(IN4_NEG) 59(LOS3) 60(OUT10) 61(OUT9) 63(OUT8) 67(OUT6_NEG) 68(OUT6_POS) 70(OUT5_NEG) 71(OUT5_POS); U76 4(NC)*; U83 11(B4)* 12(B3)*; U85 4(COM3) 6(COM4) 7(COM5)* 9(COM6)* 12(NO3) 13(NO6)* 14(NO4) 15(NO5)* 16(NC5)* 18(NC4) 19(NC6)* 20(NC3) 24(NC)*; U86 3(NC1)* 4(NC2)* 5(NC3)* 6(NC4)* 7(NC5)* 11(NC6)* 12(NC7)* 13(NC8)* 14(NC9)* 15(NC10)* 17(NC11)* 18(NC12)* 19(NC13)* 20(NC14)* 21(NC15)* 22(NC16)* 23(NC17)* 24(NC18)* 25(NC19)* 27(NC20)* 28(NC21)*; U88 5(DNC1)* 10(DNC2)*

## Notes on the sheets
sheet 43
- UNLESS OTHERWISE SPECIFIED:
  RESISTORS ARE 0402 PACKAGE, POWER RATING < 0.5W & TOLERANCE > 1%
  CAPACITORS ARE 0402 PACKAGE & TOLERANCE OF 10%
- Provision,If mSATA does not have LED indication
- mSATA 0 STATUS LED
- s
- d
- g
- g
- mSATA CONNECTOR
- d
- s
- 9774030243R
- mSATA LOAD SWITCH
- 2A MAX
- ADDRESS 45
- mSATA CURRENT MONITOR
- 2
- 1
sheet 44
- UNLESS OTHERWISE SPECIFIED:
  RESISTORS ARE 0402 PACKAGE, POWER RATING < 0.5W & TOLERANCE > 1%
  CAPACITORS ARE 0402 PACKAGE & TOLERANCE OF 10%
- CAD NOTE: PLACE C1833 AND C1834 NEAR U3C1
- CAD NOTE: PLACE C1835 AND C1836 NEAR J3M1
- Provision,If mSATA does not have LED indication
- MEM_RESET_L
- mSATA STATUS LED
- mSATA CONNECTOR
- 9774030151R
- 2
- 1
sheet 45
- BLM18BB221SN1 Murata
- Stabbility:500ppb
- TCXO=25MHZ
- to OCT GPIO47
- to OCT GPIO46
- master
- to ethsw
- XO_FREQ[2:0]=110:
- OSCI=25MHZ
- from 81xx GPIO45
- from ethsw CDR
- Place close to VC1
- Place close to VC2
- I2C MODE
- IIC ADDRESS:0X52
- Ferribte current MAX 400mA
- LDO 200mA
sheet 46
- Temp Sensor
  place close to led board connector
- ADDRESS: 0X18
- Temp Sensor 1
  place on tiva section
- 0011A2 A1 A0 X
- ADDRESS: 0X1A
- cathode
- anode
- -
- +
- address 0x5A
- 0011A2 A1 A0 X
- ADDRESS: 0X19
- Temp Sensor 1
  place on power section
- ADDRESS: 0X1C
- Temp Sensor
  place close to 81XX
- 0011A2 A1 A0 X
- ADDRESS: 0X1B
- Temp Sensor
  place on ethernet Switch
sheet 47
- UNLESS OTHERWISE SPECIFIED:
  RESISTORS ARE 0402 PACKAGE, POWER RATING < 0.5W & TOLERANCE > 1%
  CAPACITORS ARE 0402 PACKAGE & TOLERANCE OF 10%
- DEBUG OPTION
- DEBUG OPTION
sheet 48
- SPI1
- SPI
  FLASH
- TIVA
- I2C2
- MUX
- TPM
- default PATH after power on
- I2C1
- OCT-SPI
- SPI
- MUX
- SPI
  FLASH
- HEADER
- PROG
- IN1,IN2=1: COMn=NOn
  IN1,IN2=0: COMn=NCn
